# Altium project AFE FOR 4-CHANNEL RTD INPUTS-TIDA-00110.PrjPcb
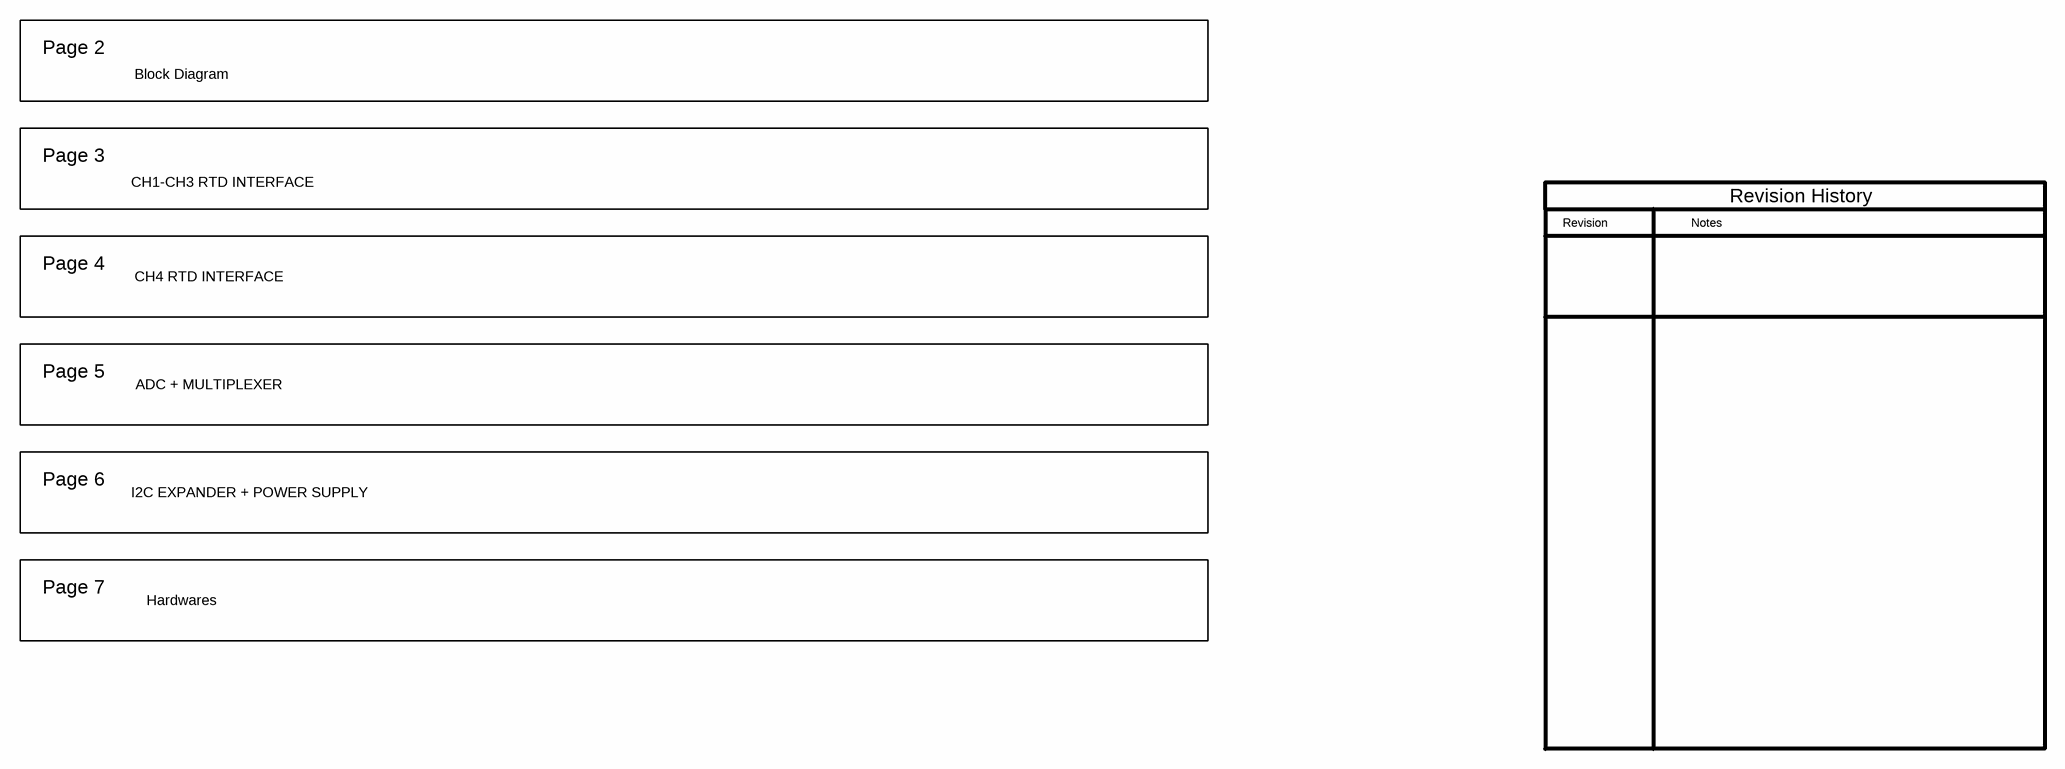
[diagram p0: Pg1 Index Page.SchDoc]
CopyrightYear: 2014; PCB_Rev: E1; PRJ_Customer: Public Release; PRJ_Engineer: Prahlad Supeda; PRJ_Number: TIDA-00110; PRJ_Title: AFE FOR 4-CHANNEL RTD INPUTS; SCH_Rev: E1; TechSupport: http://www.ti.com/support
7 sheets, 192 parts. Net scope: flat (ports and power ports of the same name join across sheets).
Board file: TIDA-00110.PcbDoc
Sheets:
  Pg1 Index Page.SchDoc
  Pg2 Block Diagram.SchDoc
  Pg3 CH1-CH3 RTD INTERFACE.SchDoc
  Pg4 CH4 RTD INTERFACE.SchDoc
  Pg5 ADC + MULTIPLEXER.SchDoc
  Pg6 I2C EXPANDER + POWER SUPPLY.SchDoc
  Pg7 Hardware.SchDoc

## Sheet Pg1 Index Page.SchDoc: Index Page
size 431 x 279 mm; Date: Not shown in title block; ApprovedBy: Not shown in title block; CheckedBy: Not shown in title block; Author: Not shown in title block; CompanyName: Not shown in title block; Engineer: Not shown in title block; Organization: Not shown in title block; Address1: Not shown in title block; Address2: Not shown in title block; Address3: Not shown in title block; Address4: Not shown in title block; DocumentNumber: 1; Revision: Use project parameter SCH_Rev; SheetNumber: 1; SheetTotal: 7; PageSetup: Record=PageOptions|CenterHorizontal=True|CenterVertical=True|PrintScale=0.62|XCorrection=1.00|YCorrection=1.00|PrintKind=0|BorderSize=5000000|LeftOffset=0|BottomOffset=0|Orientation=2|PaperLength=1000|PaperWidth=1000|Scale=100|PaperSource=15|PrintQuality=600|MediaType=1|DitherType=10|PaperKind=Letter|PrintScaleMode=1

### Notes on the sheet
- Page 2
- Block Diagram
- Page 3
- CH1-CH3 RTD INTERFACE
- Revision History
- Page 4
- Revision
- Notes
- CH4 RTD INTERFACE
- Page 5
- ADC + MULTIPLEXER
- Page 6
- I2C EXPANDER + POWER SUPPLY
- Page 7
- Hardwares

## Sheet Pg2 Block Diagram.SchDoc: Block Diagram
size 431 x 279 mm; Date: Not shown in title block; ApprovedBy: Not shown in title block; CheckedBy: Not shown in title block; Author: Not shown in title block; CompanyName: Not shown in title block; Engineer: Not shown in title block; Organization: Not shown in title block; Address1: Not shown in title block; Address2: Not shown in title block; Address3: Not shown in title block; Address4: Not shown in title block; DocumentNumber: 7; Revision: Use project parameter SCH_Rev; SheetNumber: 2; SheetTotal: 7; PageSetup: Record=PageOptions|CenterHorizontal=True|CenterVertical=True|PrintScale=1.00|XCorrection=1.00|YCorrection=1.00|PrintKind=0|BorderSize=5000000|LeftOffset=0|BottomOffset=0|Orientation=2|PaperLength=1000|PaperWidth=1000|Scale=100|PaperSource=15|PrintQuality=600|MediaType=1|DitherType=10|PaperKind=Letter|PrintScaleMode=1
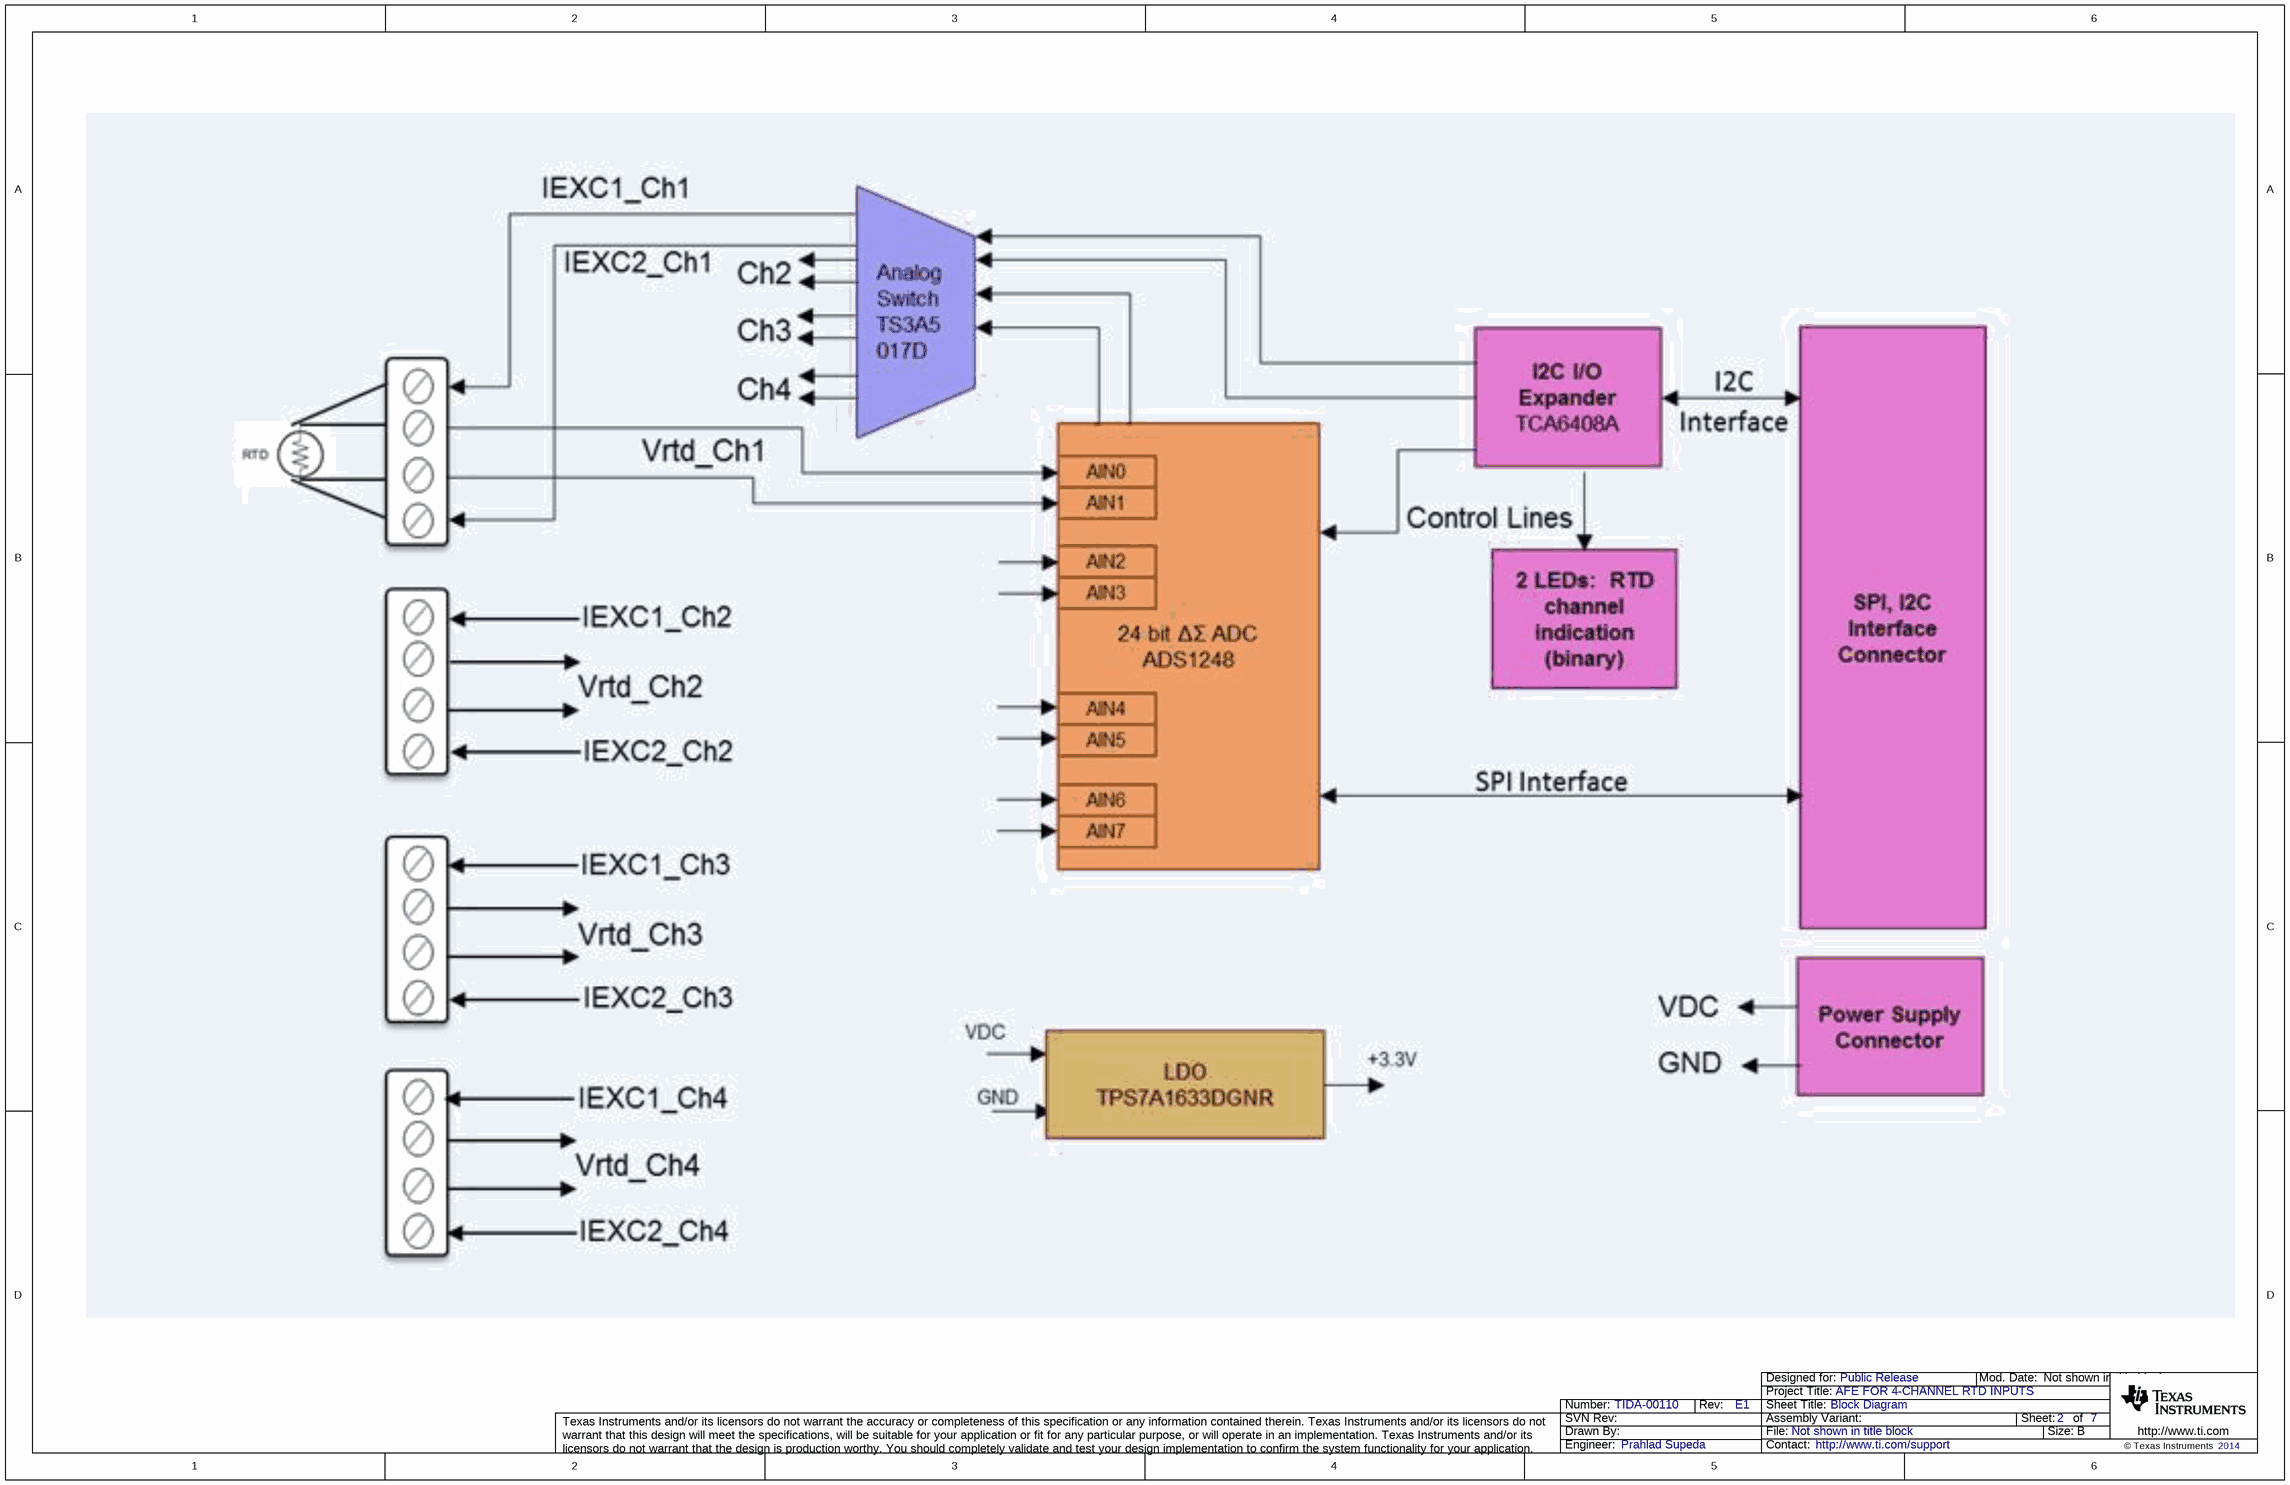
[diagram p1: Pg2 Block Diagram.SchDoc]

## Sheet Pg3 CH1-CH3 RTD INTERFACE.SchDoc: CH1-CH3 RTD INTERFACE
size 431 x 279 mm; Date: Not shown in title block; ApprovedBy: Not shown in title block; CheckedBy: Not shown in title block; Author: Not shown in title block; CompanyName: Not shown in title block; Engineer: Not shown in title block; Organization: Not shown in title block; Address1: Not shown in title block; Address2: Not shown in title block; Address3: Not shown in title block; Address4: Not shown in title block; DocumentNumber: 7; Revision: Use project parameter SCH_Rev; SheetNumber: 3; SheetTotal: 7; PageSetup: Record=PageOptions|CenterHorizontal=True|CenterVertical=True|PrintScale=0.64|XCorrection=1.00|YCorrection=1.00|PrintKind=0|BorderSize=5000000|LeftOffset=0|BottomOffset=0|Orientation=2|PaperLength=1000|PaperWidth=1000|Scale=100|PaperSource=15|PrintQuality=600|MediaType=1|DitherType=10|PaperKind=Letter|PrintScaleMode=1
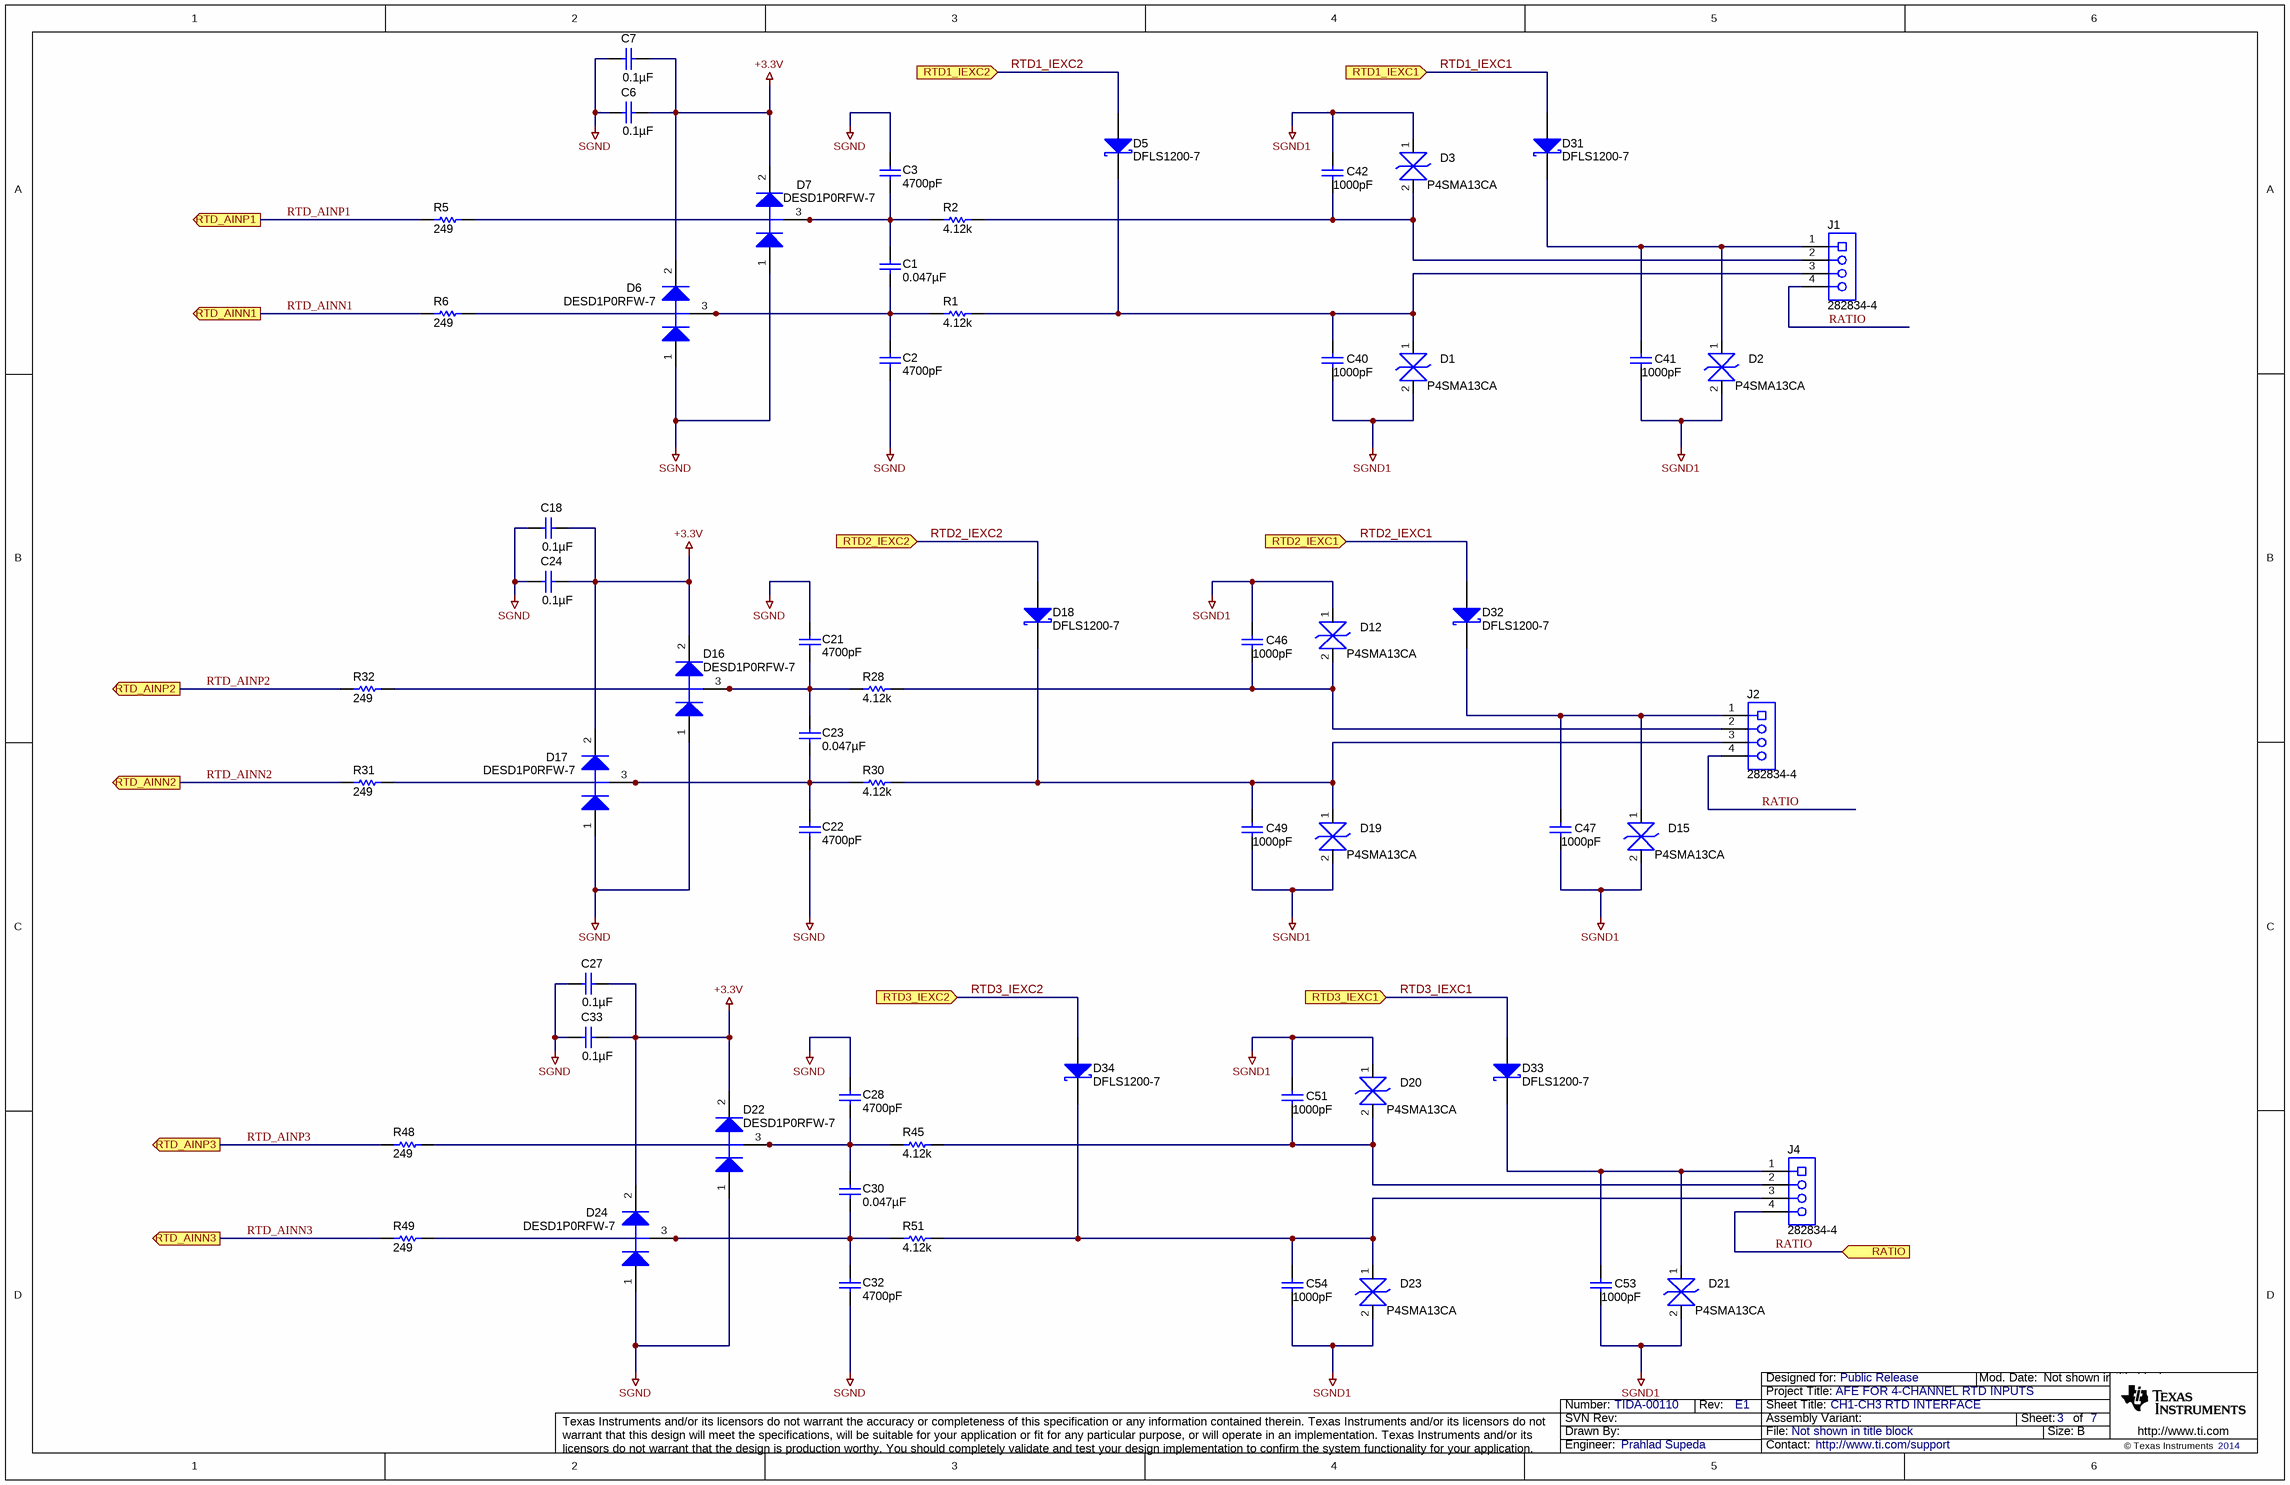
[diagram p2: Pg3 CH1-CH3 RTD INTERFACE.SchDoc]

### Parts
C1  ValueDisplayed: 0.047µF  [0603]  (hidden comment: C1608X7R1H473K)
C2  ValueDisplayed: 4700pF  [0603]  (hidden comment: C1608X8R1H472K)
C3  ValueDisplayed: 4700pF  [0603]  (hidden comment: C1608X8R1H472K)
C6  ValueDisplayed: 0.1µF  [0603]  (hidden comment: 06035C104KAT2A)
C7  ValueDisplayed: 0.1µF  [0603]  (hidden comment: 06035C104KAT2A)
C18  ValueDisplayed: 0.1µF  [0603]  (hidden comment: 06035C104KAT2A)
C21  ValueDisplayed: 4700pF  [0603]  (hidden comment: C1608X8R1H472K)
C22  ValueDisplayed: 4700pF  [0603]  (hidden comment: C1608X8R1H472K)
C23  ValueDisplayed: 0.047µF  [0603]  (hidden comment: C1608X7R1H473K)
C24  ValueDisplayed: 0.1µF  [0603]  (hidden comment: 06035C104KAT2A)
C27  ValueDisplayed: 0.1µF  [0603]  (hidden comment: 06035C104KAT2A)
C28  ValueDisplayed: 4700pF  [0603]  (hidden comment: C1608X8R1H472K)
C30  ValueDisplayed: 0.047µF  [0603]  (hidden comment: C1608X7R1H473K)
C32  ValueDisplayed: 4700pF  [0603]  (hidden comment: C1608X8R1H472K)
C33  ValueDisplayed: 0.1µF  [0603]  (hidden comment: 06035C104KAT2A)
C40  value 1000pF  [1206]  (hidden comment: CC1206KRX7R0BB102)
C41  value 1000pF  [1206]  (hidden comment: CC1206KRX7R0BB102)
C42  value 1000pF  [1206]  (hidden comment: CC1206KRX7R0BB102)
C46  value 1000pF  [1206]  (hidden comment: CC1206KRX7R0BB102)
C47  value 1000pF  [1206]  (hidden comment: CC1206KRX7R0BB102)
C49  value 1000pF  [1206]  (hidden comment: CC1206KRX7R0BB102)
C51  value 1000pF  [1206]  (hidden comment: CC1206KRX7R0BB102)
C53  value 1000pF  [1206]  (hidden comment: CC1206KRX7R0BB102)
C54  value 1000pF  [1206]  (hidden comment: CC1206KRX7R0BB102)
D1  P4SMA13CA  [DIO_DO214AC_SMA_BI]
D2  P4SMA13CA  [DIO_DO214AC_SMA_BI]
D3  P4SMA13CA  [DIO_DO214AC_SMA_BI]
D5  DFLS1200-7  [powerDI123]
D6  DESD1P0RFW-7  [SOT-323]
D7  DESD1P0RFW-7  [SOT-323]
D12  P4SMA13CA  [DIO_DO214AC_SMA_BI]
D15  P4SMA13CA  [DIO_DO214AC_SMA_BI]
D16  DESD1P0RFW-7  [SOT-323]
D17  DESD1P0RFW-7  [SOT-323]
D18  DFLS1200-7  [powerDI123]
D19  P4SMA13CA  [DIO_DO214AC_SMA_BI]
D20  P4SMA13CA  [DIO_DO214AC_SMA_BI]
D21  P4SMA13CA  [DIO_DO214AC_SMA_BI]
D22  DESD1P0RFW-7  [SOT-323]
D23  P4SMA13CA  [DIO_DO214AC_SMA_BI]
D24  DESD1P0RFW-7  [SOT-323]
D31  DFLS1200-7  [powerDI123]
D32  DFLS1200-7  [powerDI123]
D33  DFLS1200-7  [powerDI123]
D34  DFLS1200-7  [powerDI123]
J1  282834-4  [TEC_282834-4]
J2  282834-4  [TEC_282834-4]
J4  282834-4  [TEC_282834-4]
R1  value 4.12k  [0603]  (hidden comment: RG1608P-4121-B-T5)
R2  value 4.12k  [0603]  (hidden comment: RG1608P-4121-B-T5)
R5  ValueDisplayed: 249  [0603]  (hidden comment: CRCW0603249RFKEA)
R6  ValueDisplayed: 249  [0603]  (hidden comment: CRCW0603249RFKEA)
R28  value 4.12k  [0603]  (hidden comment: RG1608P-4121-B-T5)
R30  value 4.12k  [0603]  (hidden comment: RG1608P-4121-B-T5)
R31  ValueDisplayed: 249  [0603]  (hidden comment: CRCW0603249RFKEA)
R32  ValueDisplayed: 249  [0603]  (hidden comment: CRCW0603249RFKEA)
R45  value 4.12k  [0603]  (hidden comment: RG1608P-4121-B-T5)
R48  ValueDisplayed: 249  [0603]  (hidden comment: CRCW0603249RFKEA)
R49  ValueDisplayed: 249  [0603]  (hidden comment: CRCW0603249RFKEA)
R51  value 4.12k  [0603]  (hidden comment: RG1608P-4121-B-T5)

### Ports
RATIO (in), RTD1_IEXC1 (in), RTD1_IEXC2 (in), RTD2_IEXC1 (in), RTD2_IEXC2 (in), RTD3_IEXC1 (in), RTD3_IEXC2 (in), RTD_AINN1 (out), RTD_AINN2 (out), RTD_AINN3 (out), RTD_AINP1 (out), RTD_AINP2 (out), RTD_AINP3 (out)

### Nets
+3.3V: C6.1 C7.1 C18.1 C24.1 C27.1 C33.1 D6.2(K) D7.2(K) D16.2(K) D17.2(K) D22.2(K) D24.2(K)
SGND: C2.2 C3.1 C6.2 C7.2 C18.2 C21.1 C22.2 C24.2 C27.2 C28.1 C32.2 C33.2 D6.1(A) D7.1(A) D16.1(A) D17.1(A) D22.1(A) D24.1(A)
SGND1: C40.1 C41.1 C42.2 C46.2 C47.1 C49.1 C51.2 C53.1 C54.1 D1.2 D2.2 D3.1 D12.1 D15.2 D19.2 D20.1 D21.2 D23.2
RATIO: J1.4 J2.4 J4.4 ; port RATIO
RTD1_IEXC1: D31.2(A) ; port RTD1_IEXC1
RTD1_IEXC2: D5.2(A) ; port RTD1_IEXC2
RTD2_IEXC1: D32.2(A) ; port RTD2_IEXC1
RTD2_IEXC2: D18.2(A) ; port RTD2_IEXC2
RTD3_IEXC1: D33.2(A) ; port RTD3_IEXC1
RTD3_IEXC2: D34.2(A) ; port RTD3_IEXC2
RTD_AINN1: R6.1 ; port RTD_AINN1
RTD_AINN2: R31.1 ; port RTD_AINN2
RTD_AINN3: R49.1 ; port RTD_AINN3
RTD_AINP1: R5.1 ; port RTD_AINP1
RTD_AINP2: R32.1 ; port RTD_AINP2
RTD_AINP3: R48.1 ; port RTD_AINP3
NetC1_1: C1.1 C3.2 D7.3(C) R2.1 R5.2
NetC1_2: C1.2 C2.1 D6.3(C) R1.1 R6.2
NetC21_2: C21.2 C23.1 D16.3(C) R28.1 R32.2
NetC22_1: C22.1 C23.2 D17.3(C) R30.1 R31.2
NetC28_2: C28.2 C30.1 D22.3(C) R45.1 R48.2
NetC30_2: C30.2 C32.1 D24.3(C) R49.2 R51.1
NetC40_2: C40.2 D1.1 D5.1(K) J1.3 R1.2
NetC41_2: C41.2 D2.1 D31.1(K) J1.1
NetC42_1: C42.1 D3.2 J1.2 R2.2
NetC46_1: C46.1 D12.2 J2.2 R28.2
NetC47_2: C47.2 D15.1 D32.1(K) J2.1
NetC49_2: C49.2 D18.1(K) D19.1 J2.3 R30.2
NetC51_1: C51.1 D20.2 J4.2 R45.2
NetC53_2: C53.2 D21.1 D33.1(K) J4.1
NetC54_2: C54.2 D23.1 D34.1(K) J4.3 R51.2

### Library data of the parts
C1 C23 C30 = C1608X7R1H473K: CAP, CERM, 0.047uF, 50V, +/-10%, X7R, 0603; Manufacturer: TDK; Polarized: N; CompType: Capacitor; U/M: EA; Cap_F: 0.000000047; Tolerance_%: 10; ESR_Ohm: 0.0234; Value1: 0.0234 ohm; VDC_V: 50; TaMin_C: -55; TaMax_C: 125
C2 C3 C21 C22 C28 C32 = C1608X8R1H472K: CAP, CERM, 4700pF, 50V, +/-10%, X8R, 0603; Manufacturer: TDK; Polarized: N; CompType: Capacitor; U/M: EA; Cap_F: 0.0000000047; Tolerance_%: 10; ESR_Ohm: 0.0973; Value1: 0.0973 ohm; VDC_V: 50; TaMin_C: -55; TaMax_C: 150
C6 C7 C18 C24 C27 C33 = C0603C104K5RACTU: CAP, CERM, 0.1uF, 50V, +/-10%, X7R, 0603; Manufacturer: AVX; Polarized: N; CompType: Capacitor; U/M: EA; Cap_F: 0.0000001; Tolerance_%: 10; Value1: Unknown; VDC_V: 50; TaMin_C: -55; TaMax_C: 125
C40-C42 C46 C47 C49 C51 C53 C54 = 202R18W102KV4E: CAP CER 1000PF 100V 10% X7R 1206; Manufacturer: Yageo; Polarized: N; CompType: Capacitor; Cap_F: 0.000000001; Tolerance_%: 0; Value2: 2KV
D1-D3 D12 D15 D19-D21 D23 = SMBJ18CA: TVS DIODE 11.1VWM 18.2VC SMD; Manufacturer: Littelfuse Inc
D5 D18 D31-D34 = DFLS1200-7: Diode, Schotky, 200V, 1A, PowerDI123; Manufacturer: DIODES  INCORPORATED; U/M: EA; Vf_V: 0.85; Value2: 0.85V; Io_A: 1; Vr_V: 200; TJmax_C: 175; RJC_CperW: 7; Type: Schottky
D6 D7 D16 D17 D22 D24 = BAV99WT1G: TVS DIODE,70VVVM,8VC,SOT-323; Manufacturer: DIODES INCORPORATED; Type: P-N; Value: DNP
J1 J2 J4 = 282834-4: Receptacle, 100mil, 4X1 TH; Manufacturer: TE Connectivity; SymbolCreator: a0411947; U/M: EA
R1 R2 R28 R30 R45 R51 = RG1608P-4121-B-T5: RES, 4.12k ohm, 0.1%, 0.1W, 0603; Manufacturer: Susumu Co Ltd; CompType: Resistor; Res_ohm: 4120; Value_Code: 4k12; Tolerance_%: 0.1; VDC_V: 75; TempCo: 25 ppm/C; EIA_Code: E192; U/M: EA
R5 R6 R31 R32 R48 R49 = CRCW0603249RFKEA: RES, 249, 1%, 0.1 W, 0603; Manufacturer: Vishay-Dale; CompType: Resistor; Value: 249; Value_Code: 249R; Tolerance_%: 1; Power_W: 0.1; Value2: 0.1W; VDC_V: 75; TempCo: 100 ppm/C; EIA_Code: E96; U/M: EA

## Sheet Pg4 CH4 RTD INTERFACE.SchDoc: CH4 RTD INTERFACE
size 431 x 279 mm; Date: Not shown in title block; ApprovedBy: Not shown in title block; CheckedBy: Not shown in title block; Author: Not shown in title block; CompanyName: Not shown in title block; Engineer: Not shown in title block; Organization: Not shown in title block; Address1: Not shown in title block; Address2: Not shown in title block; Address3: Not shown in title block; Address4: Not shown in title block; DocumentNumber: 7; Revision: Use project parameter SCH_Rev; SheetNumber: 4; SheetTotal: 7; PageSetup: Record=PageOptions|CenterHorizontal=True|CenterVertical=True|PrintScale=1.00|XCorrection=1.00|YCorrection=1.00|PrintKind=0|BorderSize=5000000|LeftOffset=0|BottomOffset=0|Orientation=2|PaperLength=1000|PaperWidth=1000|Scale=100|PaperSource=15|PrintQuality=600|MediaType=1|DitherType=10|PaperKind=Letter|PrintScaleMode=1
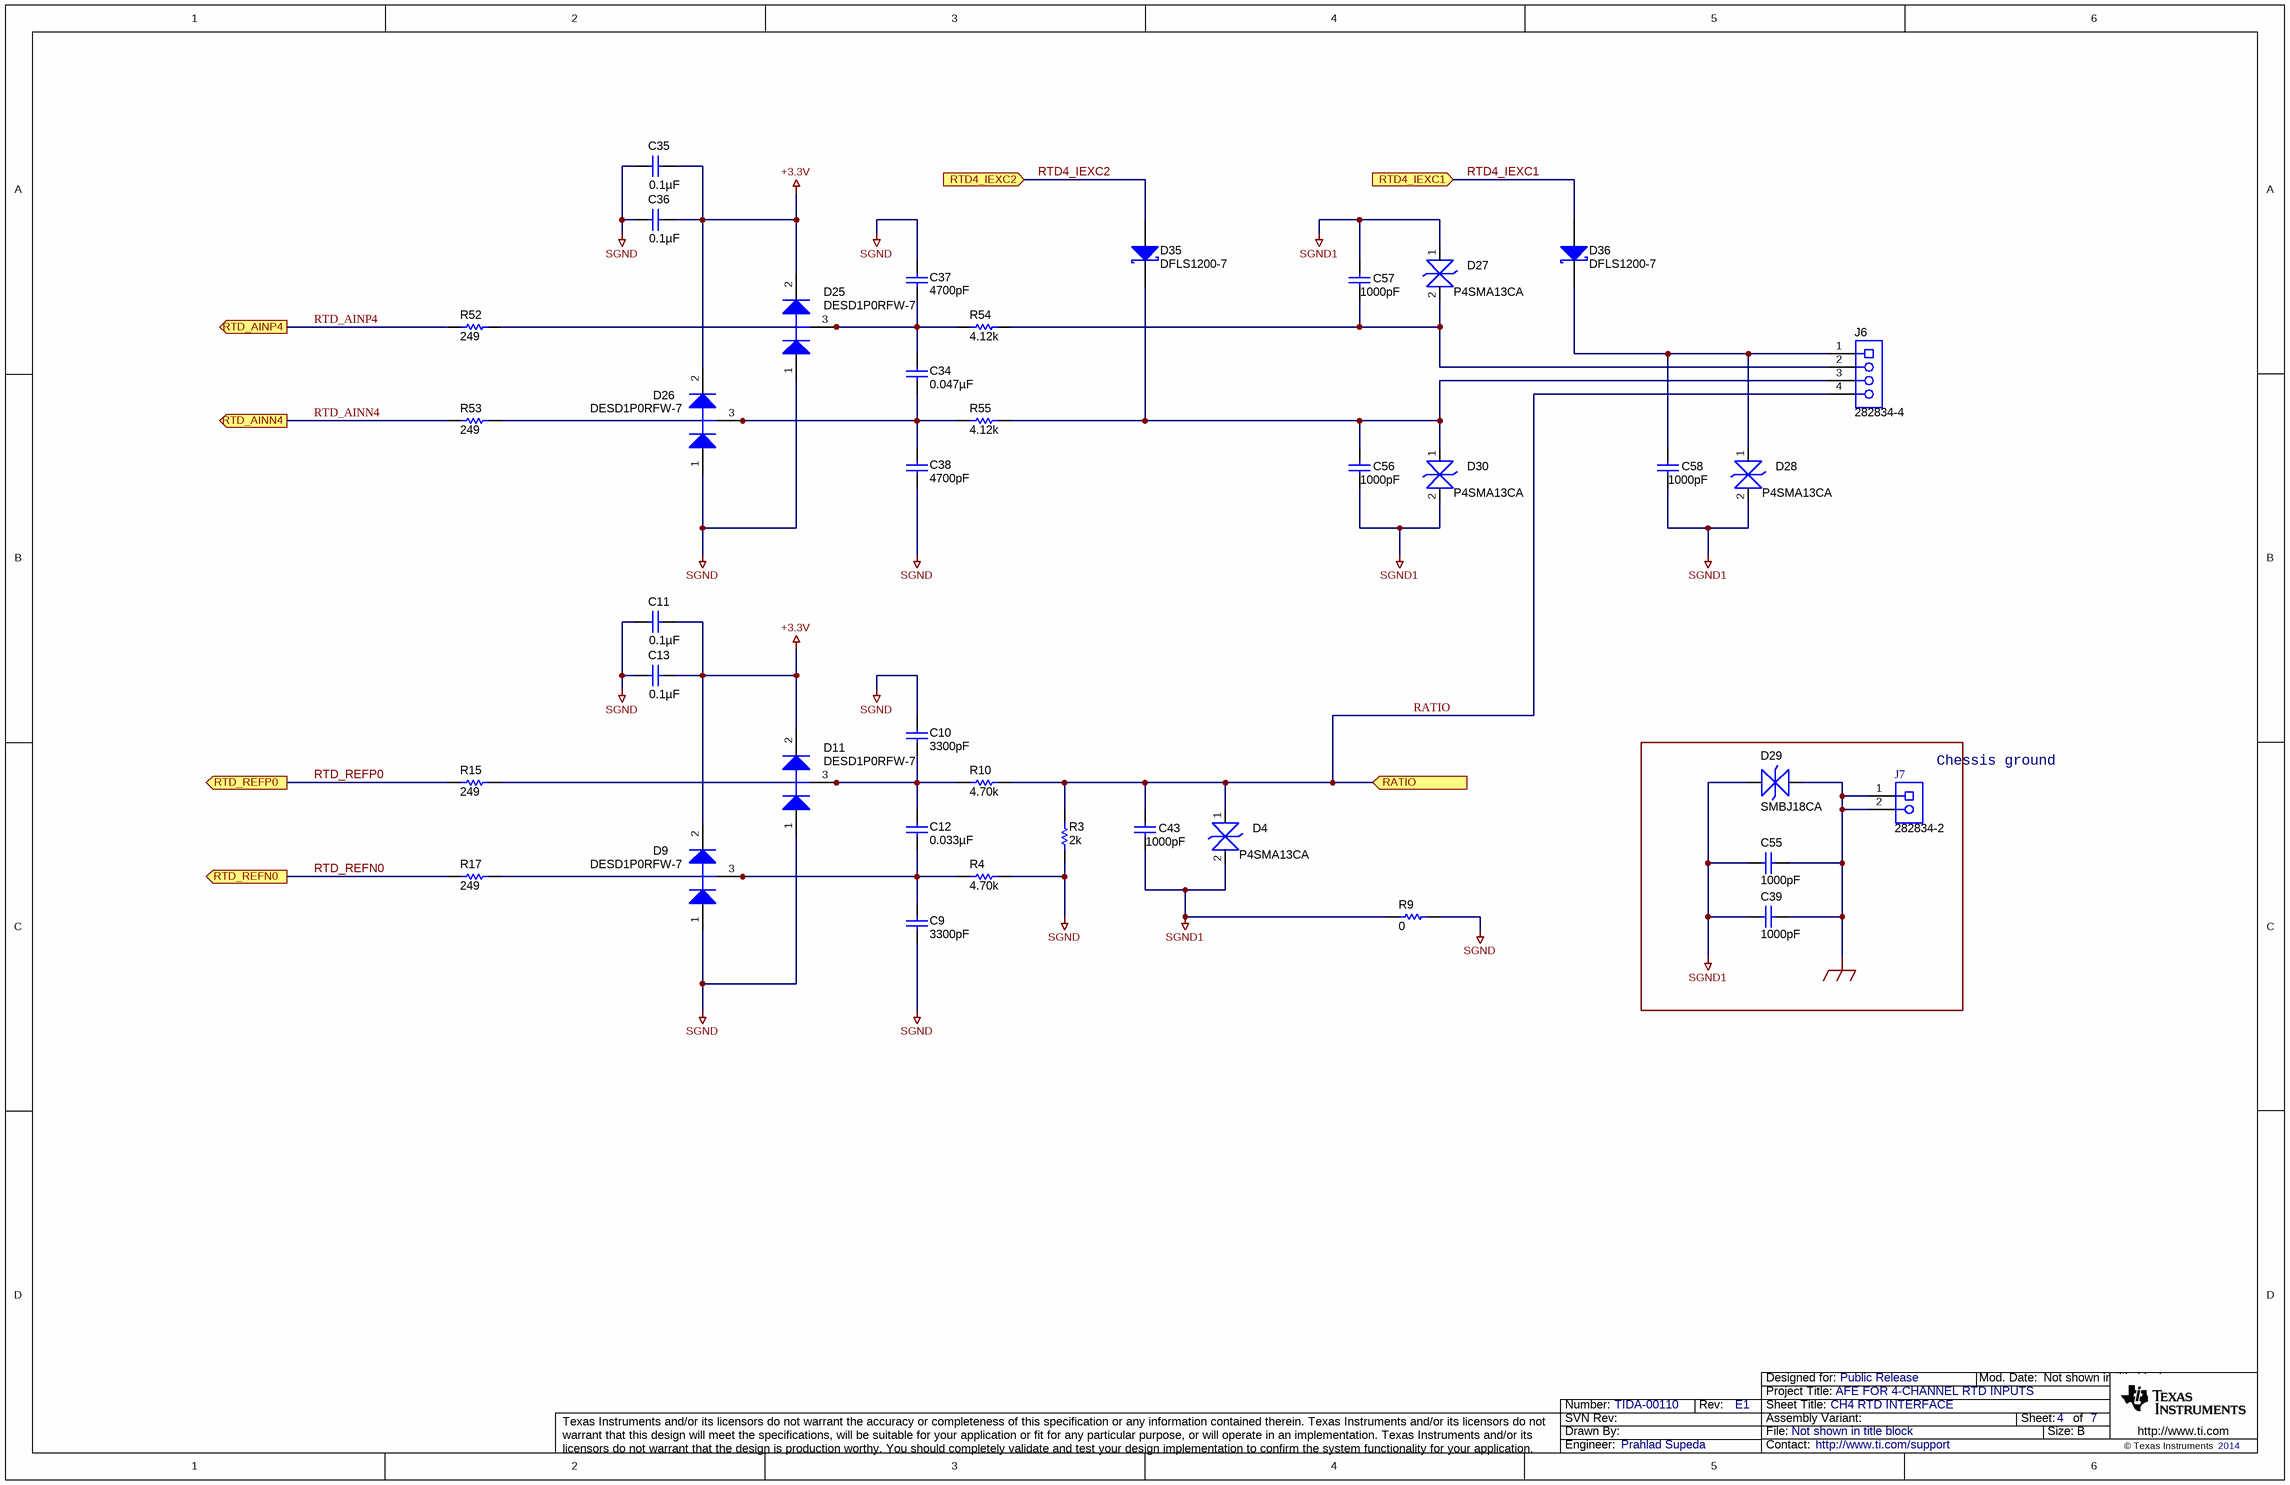
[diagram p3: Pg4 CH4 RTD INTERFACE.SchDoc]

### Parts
C9  ValueDisplayed: 3300pF  [0603]  (hidden comment: C0603C332K5RACTU)
C10  ValueDisplayed: 3300pF  [0603]  (hidden comment: C0603C332K5RACTU)
C11  ValueDisplayed: 0.1µF  [0603]  (hidden comment: 06035C104KAT2A)
C12  ValueDisplayed: 0.033µF  [0603]  (hidden comment: GRM188R71H333KA61D)
C13  ValueDisplayed: 0.1µF  [0603]  (hidden comment: 06035C104KAT2A)
C34  ValueDisplayed: 0.047µF  [0603]  (hidden comment: C1608X7R1H473K)
C35  ValueDisplayed: 0.1µF  [0603]  (hidden comment: 06035C104KAT2A)
C36  ValueDisplayed: 0.1µF  [0603]  (hidden comment: 06035C104KAT2A)
C37  ValueDisplayed: 4700pF  [0603]  (hidden comment: C1608X8R1H472K)
C38  ValueDisplayed: 4700pF  [0603]  (hidden comment: C1608X8R1H472K)
C39  value 1000pF  [1206]  (hidden comment: 202R18W102KV4E)
C43  value 1000pF  [1206]  (hidden comment: CC1206KRX7R0BB102)
C55  value 1000pF  [1206]  (hidden comment: 202R18W102KV4E)
C56  value 1000pF  [1206]  (hidden comment: CC1206KRX7R0BB102)
C57  value 1000pF  [1206]  (hidden comment: CC1206KRX7R0BB102)
C58  value 1000pF  [1206]  (hidden comment: CC1206KRX7R0BB102)
D4  P4SMA13CA  [DIO_DO214AC_SMA_BI]
D9  DESD1P0RFW-7  [SOT-323]
D11  DESD1P0RFW-7  [SOT-323]
D25  DESD1P0RFW-7  [SOT-323]
D26  DESD1P0RFW-7  [SOT-323]
D27  P4SMA13CA  [DIO_DO214AC_SMA_BI]
D28  P4SMA13CA  [DIO_DO214AC_SMA_BI]
D29  SMBJ18CA  [DIO_SMB_BIAAAA]
D30  P4SMA13CA  [DIO_DO214AC_SMA_BI]
D35  DFLS1200-7  [powerDI123]
D36  DFLS1200-7  [powerDI123]
J6  282834-4  [TEC_282834-4]
J7  282834-2  [TEC_282834-2]
R3  value 2k  [1206]  (hidden comment: TNPW12062K00BEEA)
R4  value 4.70k  [0603]  (hidden comment: RG1608P-472-B-T5)
R9  value 0  [0805_HV]  (hidden comment: RC0805JR-070RL)
R10  value 4.70k  [0603]  (hidden comment: RG1608P-472-B-T5)
R15  ValueDisplayed: 249  [0603]  (hidden comment: CRCW0603249RFKEA)
R17  ValueDisplayed: 249  [0603]  (hidden comment: CRCW0603249RFKEA)
R52  ValueDisplayed: 249  [0603]  (hidden comment: CRCW0603249RFKEA)
R53  ValueDisplayed: 249  [0603]  (hidden comment: CRCW0603249RFKEA)
R54  value 4.12k  [0603]  (hidden comment: RG1608P-4121-B-T5)
R55  value 4.12k  [0603]  (hidden comment: RG1608P-4121-B-T5)

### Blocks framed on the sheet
Chessis ground: C39 C55 D29 J7

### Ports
RATIO (in), RTD4_IEXC1 (in), RTD4_IEXC2 (in), RTD_AINN4 (out), RTD_AINP4 (out), RTD_REFN0 (out), RTD_REFP0 (out)

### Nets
+3.3V: C11.1 C13.1 C35.1 C36.1 D9.2(K) D11.2(K) D25.2(K) D26.2(K)
GND_EARTH: C39.2 C55.2 D29.2 J7.1 J7.2
SGND: C9.2 C10.1 C11.2 C13.2 C35.2 C36.2 C37.1 C38.2 D9.1(A) D11.1(A) D25.1(A) D26.1(A) R3.1 R4.2 R9.2
SGND1: C39.1 C43.1 C55.1 C56.1 C57.2 C58.1 D4.2 D27.1 D28.2 D29.1 D30.2 R9.1
RATIO: C43.2 D4.1 J6.4 R3.2 R10.2 ; port RATIO
RTD4_IEXC1: D36.2(A) ; port RTD4_IEXC1
RTD4_IEXC2: D35.2(A) ; port RTD4_IEXC2
RTD_AINN4: R53.1 ; port RTD_AINN4
RTD_AINP4: R52.1 ; port RTD_AINP4
RTD_REFN0: R17.1 ; port RTD_REFN0
RTD_REFP0: R15.1 ; port RTD_REFP0
NetC9_1: C9.1 C12.2 D9.3(C) R4.1 R17.2
NetC10_2: C10.2 C12.1 D11.3(C) R10.1 R15.2
NetC34_1: C34.1 C37.2 D25.3(C) R52.2 R54.1
NetC34_2: C34.2 C38.1 D26.3(C) R53.2 R55.1
NetC56_2: C56.2 D30.1 D35.1(K) J6.3 R55.2
NetC57_1: C57.1 D27.2 J6.2 R54.2
NetC58_2: C58.2 D28.1 D36.1(K) J6.1

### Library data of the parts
C9 C10 = C0603C332K5RACTU: CAP, CERM, 3300pF, 50V, +/-10%, X7R, 0603; Manufacturer: Kemet; Polarized: N; CompType: Capacitor; U/M: EA; Cap_F: 0.0000000033; Tolerance_%: 10; Value1: Unknown; VDC_V: 50; TaMin_C: -55; TaMax_C: 125
C11 C13 C35 C36 = C0603C104K5RACTU: as C6 on sheet Pg3 CH1-CH3 RTD INTERFACE
C12 = GRM188R71H333KA61D: CAP, CERM, 0.033uF, 50V, +/-10%, X7R, 0603; Manufacturer: MuRata; Polarized: N; CompType: Capacitor; U/M: EA; Cap_F: 0.000000033; Tolerance_%: 10; Value1: Unknown; VDC_V: 50; TaMin_C: -55; TaMax_C: 125
C34 = C1608X7R1H473K: as C1 on sheet Pg3 CH1-CH3 RTD INTERFACE
C37 C38 = C1608X8R1H472K: as C2 on sheet Pg3 CH1-CH3 RTD INTERFACE
C39 C55 = 202R18W102KV4E: CAP, CERM, 1000pF, 2KV 10% X7R 1206; Manufacturer: Johanson Dielectrics Inc; Polarized: N; CompType: Capacitor; Cap_F: 0.000000001; Tolerance_%: 0
C43 C56-C58 = 202R18W102KV4E: as C40 on sheet Pg3 CH1-CH3 RTD INTERFACE
D4 D27 D28 D30 = SMBJ18CA: as D1 on sheet Pg3 CH1-CH3 RTD INTERFACE
D9 D11 D25 D26 = BAV99WT1G: as D6 on sheet Pg3 CH1-CH3 RTD INTERFACE
D29 = SMBJ18CA: TVS 18 VOLT 600 WATT BI-DIR SMB; Manufacturer: Littelfuse Inc
D35 D36 = DFLS1200-7: as D5 on sheet Pg3 CH1-CH3 RTD INTERFACE
J6 = 282834-4: as J1 on sheet Pg3 CH1-CH3 RTD INTERFACE
J7 = 282834-2: Terminal Block, 2x1, 2.54mm, TH; Manufacturer: TE Connectivity; SymbolCreator: a0412235; U/M: EA
R3 = CRCW12062K49FKEA: RES 2K OHM 1/4W 0.1% 1206; Manufacturer: Vishay-Dale; CompType: Resistor; Res_ohm: 2490; Value_Code: 2k49; Tolerance_%: 1; Power_W: 0.25; Value2: 0.25W; VDC_V: 200; TempCo: 100 ppm/C; EIA_Code: E96; U/M: EA
R4 R10 = RG1608P-472-B-T5: RES, 4.70k ohm, 0.1%, 0.1W, 0603; Manufacturer: Susumu Co Ltd; CompType: Resistor; Res_ohm: 4700; Value_Code: 4k70; Tolerance_%: 0.1; VDC_V: 75; TempCo: 25 ppm/C; EIA_Code: E192; U/M: EA
R9 = RC0805JR-070RL: RES, 0 ohm, 5%, 0.125W, 0805; Manufacturer: Yageo America; CompType: Resistor; Value_Code: 0000; Tolerance_%: 5; Power_W: 0.125; VDC_V: 150; TempCo: 200 ppm/C; EIA_Code: E24; U/M: EA
R15 R17 R52 R53 = CRCW0603249RFKEA: as R5 on sheet Pg3 CH1-CH3 RTD INTERFACE
R54 R55 = RG1608P-4121-B-T5: as R1 on sheet Pg3 CH1-CH3 RTD INTERFACE

## Sheet Pg5 ADC + MULTIPLEXER.SchDoc: ADC + MULTIPLEXER
size 431 x 279 mm; Date: Not shown in title block; ApprovedBy: Not shown in title block; CheckedBy: Not shown in title block; Author: Not shown in title block; CompanyName: Not shown in title block; Engineer: Not shown in title block; Organization: Not shown in title block; Address1: Not shown in title block; Address2: Not shown in title block; Address3: Not shown in title block; Address4: Not shown in title block; DocumentNumber: 7; Revision: Use project parameter SCH_Rev; SheetNumber: 5; SheetTotal: 7; PageSetup: Record=PageOptions|CenterHorizontal=True|CenterVertical=True|PrintScale=1.00|XCorrection=1.00|YCorrection=1.00|PrintKind=0|BorderSize=5000000|LeftOffset=0|BottomOffset=0|Orientation=2|PaperLength=1000|PaperWidth=1000|Scale=100|PaperSource=15|PrintQuality=600|MediaType=1|DitherType=10|PaperKind=Letter|PrintScaleMode=1
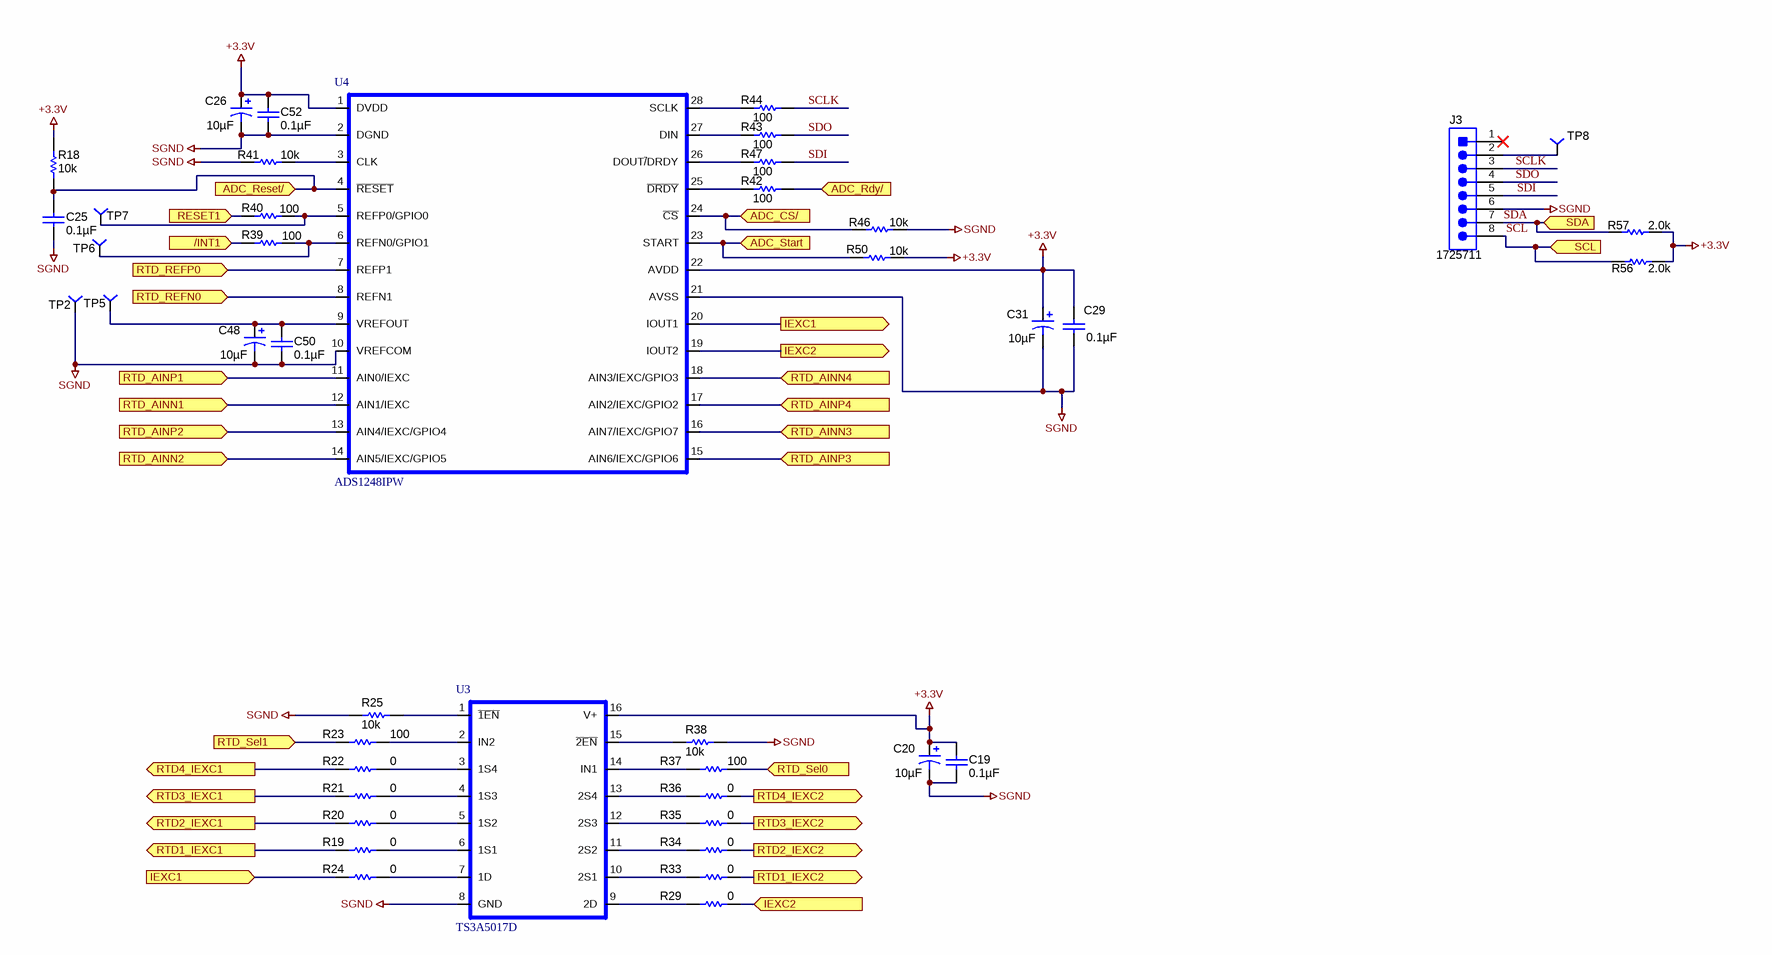
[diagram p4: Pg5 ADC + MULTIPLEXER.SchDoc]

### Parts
C19  ValueDisplayed: 0.1µF  [0603]  (hidden comment: 06035C104KAT2A)
C20  ValueDisplayed: 10µF  [3528-21]  (hidden comment: F931C106KBA)
C25  ValueDisplayed: 0.1µF  [0603]  (hidden comment: 06035C104KAT2A)
C26  ValueDisplayed: 10µF  [3528-21]  (hidden comment: F931C106KBA)
C29  ValueDisplayed: 0.1µF  [0603]  (hidden comment: 06035C104KAT2A)
C31  ValueDisplayed: 10µF  [3528-21]  (hidden comment: F931C106KBA)
C48  ValueDisplayed: 10µF  [3528-21]  (hidden comment: F931C106KBA)
C50  ValueDisplayed: 0.1µF  [0603]  (hidden comment: 06035C104KAT2A)
C52  ValueDisplayed: 0.1µF  [0603]  (hidden comment: 06035C104KAT2A)
J3  1725711  [CONN_1725711]
R18  ValueDisplayed: 10k  [0603]  (hidden comment: CRCW060310K0JNEA)
R19  ValueDisplayed: 0  [0603]  (hidden comment: CRCW06030000Z0EA)
R20  ValueDisplayed: 0  [0603]  (hidden comment: CRCW06030000Z0EA)
R21  ValueDisplayed: 0  [0603]  (hidden comment: CRCW06030000Z0EA)
R22  ValueDisplayed: 0  [0603]  (hidden comment: CRCW06030000Z0EA)
R23  ValueDisplayed: 100  [0603]  (hidden comment: CRCW0603100RFKEA)
R24  ValueDisplayed: 0  [0603]  (hidden comment: CRCW06030000Z0EA)
R25  ValueDisplayed: 10k  [0603]  (hidden comment: CRCW060310K0JNEA)
R29  ValueDisplayed: 0  [0603]  (hidden comment: CRCW06030000Z0EA)
R33  ValueDisplayed: 0  [0603]  (hidden comment: CRCW06030000Z0EA)
R34  ValueDisplayed: 0  [0603]  (hidden comment: CRCW06030000Z0EA)
R35  ValueDisplayed: 0  [0603]  (hidden comment: CRCW06030000Z0EA)
R36  ValueDisplayed: 0  [0603]  (hidden comment: CRCW06030000Z0EA)
R37  ValueDisplayed: 100  [0603]  (hidden comment: CRCW0603100RFKEA)
R38  ValueDisplayed: 10k  [0603]  (hidden comment: CRCW060310K0JNEA)
R39  ValueDisplayed: 100  [0603]  (hidden comment: CRCW0603100RFKEA)
R40  ValueDisplayed: 100  [0603]  (hidden comment: CRCW0603100RFKEA)
R41  ValueDisplayed: 10k  [0603]  (hidden comment: CRCW060310K0JNEA)
R42  ValueDisplayed: 100  [0603]  (hidden comment: CRCW0603100RFKEA)
R43  ValueDisplayed: 100  [0603]  (hidden comment: CRCW0603100RFKEA)
R44  ValueDisplayed: 100  [0603]  (hidden comment: CRCW0603100RFKEA)
R46  ValueDisplayed: 10k  [0603]  (hidden comment: CRCW060310K0JNEA)
R47  ValueDisplayed: 100  [0603]  (hidden comment: CRCW0603100RFKEA)
R50  ValueDisplayed: 10k  [0603]  (hidden comment: CRCW060310K0JNEA)
R56  ValueDisplayed: 2.0k  [0603]  (hidden comment: RC0603JR-072KL)
R57  ValueDisplayed: 2.0k  [0603]  (hidden comment: RC0603JR-072KL)
TP2  TP-038  [TP1_PD40_D0.5_S50]  (value not drawn)
TP5  TP-038  [TP1_PD40_D0.5_S50]  (value not drawn)
TP6  TP-038  [TP1_PD40_D0.5_S50]  (value not drawn)
TP7  TP-038  [TP1_PD40_D0.5_S50]  (value not drawn)
TP8  TP-038  [TP1_PD40_D0.5_S50]  (value not drawn)
U3  TS3A5017D  [SO16]
U4  ADS1248IPW  [PW28]

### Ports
/INT1 (in), ADC_CS/ (in), ADC_Rdy/ (in), ADC_Reset/ (in), ADC_Start (in), IEXC1 (in), IEXC1 (out), IEXC2 (in), IEXC2 (out), RESET1 (in), RTD1_IEXC1 (out), RTD1_IEXC2 (out), RTD2_IEXC1 (out), RTD2_IEXC2 (out), RTD3_IEXC1 (out), RTD3_IEXC2 (out), RTD4_IEXC1 (out), RTD4_IEXC2 (out), RTD_AINN1 (in), RTD_AINN2 (in), RTD_AINN3 (in), RTD_AINN4 (in), RTD_AINP1 (in), RTD_AINP2 (in), RTD_AINP3 (in), RTD_AINP4 (in), RTD_REFN0 (in), RTD_REFP0 (in), RTD_Sel0 (in), RTD_Sel1 (in), SCL (in), SDA (in)

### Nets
+3.3V: C19.1 C20.1(+) C26.1(+) C29.1 C31.1(+) C52.1 R18.1 R50.1 R56.2 R57.2 U3.16(V+) U4.1(DVDD) U4.22(AVDD)
SGND: C19.2 C20.2(-) C25.2 C26.2(-) C29.2 C31.2(-) C48.2(-) C50.2 C52.2 J3.6 R25.2 R38.1 R41.2 R46.1 TP2.1 U3.8(GND) U4.2(DGND) U4.10(VREFCOM) U4.21(AVSS)
/INT1: R39.1 ; port /INT1
ADC_CS/: R46.2 U4.24(~{CS}) ; port ADC_CS/
ADC_Rdy/: R42.2 ; port ADC_Rdy/
ADC_Reset/: C25.1 R18.2 U4.4(~{RESET}) ; port ADC_Reset/
ADC_Start: R50.2 U4.23(START) ; port ADC_Start
IEXC1: R24.1 U4.20(IOUT1) ; port IEXC1
IEXC2: R29.2 U4.19(IOUT2) ; port IEXC2
RESET1: R40.1 ; port RESET1
RTD1_IEXC1: R19.1 ; port RTD1_IEXC1
RTD1_IEXC2: R33.2 ; port RTD1_IEXC2
RTD2_IEXC1: R20.1 ; port RTD2_IEXC1
RTD2_IEXC2: R34.2 ; port RTD2_IEXC2
RTD3_IEXC1: R21.1 ; port RTD3_IEXC1
RTD3_IEXC2: R35.2 ; port RTD3_IEXC2
RTD4_IEXC1: R22.1 ; port RTD4_IEXC1
RTD4_IEXC2: R36.2 ; port RTD4_IEXC2
RTD_AINN1: U4.12(AIN1/IEXC) ; port RTD_AINN1
RTD_AINN2: U4.14(AIN5/IEXC/GPIO5) ; port RTD_AINN2
RTD_AINN3: U4.16(AIN7/IEXC/GPIO7) ; port RTD_AINN3
RTD_AINN4: U4.18(AIN3/IEXC/GPIO3) ; port RTD_AINN4
RTD_AINP1: U4.11(AIN0/IEXC) ; port RTD_AINP1
RTD_AINP2: U4.13(AIN4/IEXC/GPIO4) ; port RTD_AINP2
RTD_AINP3: U4.15(AIN6/IEXC/GPIO6) ; port RTD_AINP3
RTD_AINP4: U4.17(AIN2/IEXC/GPIO2) ; port RTD_AINP4
RTD_REFN0: U4.8(REFN1) ; port RTD_REFN0
RTD_REFP0: U4.7(REFP1) ; port RTD_REFP0
RTD_Sel0: R37.2 ; port RTD_Sel0
RTD_Sel1: R23.1 ; port RTD_Sel1
SCL: J3.8 R56.1 ; port SCL
SCLK: J3.3 R44.2
SDA: J3.7 R57.1 ; port SDA
SDI: J3.5 R47.2
SDO: J3.4 R43.2
NetC48_1: C48.1(+) C50.1 TP5.1 U4.9(VREFOUT)
NetJ3_2: J3.2 TP8.1
NetR19_2: R19.2 U3.6(1S1)
NetR20_2: R20.2 U3.5(1S2)
NetR21_2: R21.2 U3.4(1S3)
NetR22_2: R22.2 U3.3(1S4)
NetR23_2: R23.2 U3.2(IN2)
NetR24_2: R24.2 U3.7(1D)
NetR25_1: R25.1 U3.1(~{1EN})
NetR29_1: R29.1 U3.9(2D)
NetR33_1: R33.1 U3.10(2S1)
NetR34_1: R34.1 U3.11(2S2)
NetR35_1: R35.1 U3.12(2S3)
NetR36_1: R36.1 U3.13(2S4)
NetR37_1: R37.1 U3.14(IN1)
NetR38_2: R38.2 U3.15(~{2EN})
NetR39_2: R39.2 TP6.1 U4.6(REFN0/GPIO1)
NetR40_2: R40.2 TP7.1 U4.5(REFP0/GPIO0)
NetR41_1: R41.1 U4.3(CLK)
NetR42_1: R42.1 U4.25(~{DRDY})
NetR43_1: R43.1 U4.27(DIN)
NetR44_1: R44.1 U4.28(SCLK)
NetR47_1: R47.1 U4.26(DOUT~{/}DRDY)

Not connected (* = marked no-connect by the designer): J3 1*

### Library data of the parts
C19 C29 C50 C52 = 06035C104KAT2A: CAP, CERM, 0.1uF, 50V, +/-10%, X7R, 0603; Manufacturer: AVX; Polarized: N; CompType: Capacitor; U/M: EA; Cap_F: 0.0000001; Tolerance_%: 10; Value1: Unknown; VDC_V: 50; TaMin_C: -55; TaMax_C: 125
C20 C26 C31 C48 = 293D106X9016B2TE3: CAP, TA, 10 µF, 16 V, +/- 10%, 2 ohm, SMD; Manufacturer: AVX; Polarized: Y; CompType: Capacitor; Value: 10uF; U/M: EA; Cap_F: 0.00001; Tolerance_%: 10; Value1: 2 ohm; VDC_V: 16; Value2: 16V; ESR_ohm: 2; IRMS_A: 0.21; TaMin_C: -55; TaMax_C: 125; Cap_Case: B
C25 = C0603C104K5RACTU: as C6 on sheet Pg3 CH1-CH3 RTD INTERFACE
J3 = 1725711: Terminal Block, 8x1, 2.54 mm, TH; Manufacturer: Phoenix Contact; SymbolCreator: a0411947; U/M: EA
R18 R25 R38 R41 R46 R50 = CRCW060310K0JNEA: RES, 10 k, 5%, 0.1 W, 0603; Manufacturer: Vishay-Dale; CompType: Resistor; Res_ohm: 10000; Value: 10k; Value_Code: 10k0; Tolerance_%: 5; Power_W: 0.1; Value2: 0.1W; VDC_V: 75; TempCo: 200 ppm/C; EIA_Code: E24; U/M: EA
R19-R22 R24 R29 R33-R36 = CRCW06030000Z0EA: RES, 0, 5%, 0.1 W, 0603; Manufacturer: Vishay-Dale; CompType: Resistor; Value: 0; Value_Code: 0000; Tolerance_%: 5; Power_W: 0.1; Value2: 0.1W; VDC_V: 75; TempCo: 200 ppm/C; EIA_Code: E24; U/M: EA
R23 R37 R39 R40 R42-R44 R47 = CRCW0603100RFKEA: RES, 100, 1%, 0.1 W, 0603; Manufacturer: Vishay-Dale; CompType: Resistor; Value: 100; Value_Code: 100R; Tolerance_%: 1; Power_W: 0.1; Value2: 0.1W; VDC_V: 75; TempCo: 100 ppm/C; EIA_Code: E96; U/M: EA
R56 R57 = RC0603JR-072KL: RES, 2.0 k, 5%, 0.1 W, 0603; Manufacturer: Yageo America; CompType: Resistor; Res_ohm: 2000; Value: 2.0k; Value_Code: 2k00; Tolerance_%: 5; Power_W: 0.1; Value2: 0.1W; VDC_V: 50; TempCo: 100 ppm/C; EIA_Code: E24; U/M: EA
TP2 TP5-TP8 = TP-038: Test Point 40mil pad 20mil drill; Manufacturer: STD; Value: STD
U3 = TS3A5017D: IC, Dual, 14 Ohms SP4T Analog Switch; Manufacturer: TI; Alternate Manufacturer: None; AREA: 145200
U4 = ADS1248IPW: IC, 24-Bit A-D Converters for Temperature Sensors; Manufacturer: TI; Alternate Manufacturer: None; Area: 164.280

## Sheet Pg6 I2C EXPANDER + POWER SUPPLY.SchDoc: I2C EXPANDER + POWER SUPPLY
size 431 x 279 mm; Date: Not shown in title block; ApprovedBy: Not shown in title block; CheckedBy: Not shown in title block; Author: Not shown in title block; CompanyName: Not shown in title block; Engineer: Not shown in title block; Organization: Not shown in title block; Address1: Not shown in title block; Address2: Not shown in title block; Address3: Not shown in title block; Address4: Not shown in title block; DocumentNumber: 7; Revision: Use project parameter SCH_Rev; SheetNumber: 6; SheetTotal: 7; PageSetup: Record=PageOptions|CenterHorizontal=True|CenterVertical=True|PrintScale=1.00|XCorrection=1.00|YCorrection=1.00|PrintKind=0|BorderSize=5000000|LeftOffset=0|BottomOffset=0|Orientation=2|PaperLength=1000|PaperWidth=1000|Scale=100|PaperSource=15|PrintQuality=600|MediaType=1|DitherType=10|PaperKind=Letter|PrintScaleMode=1
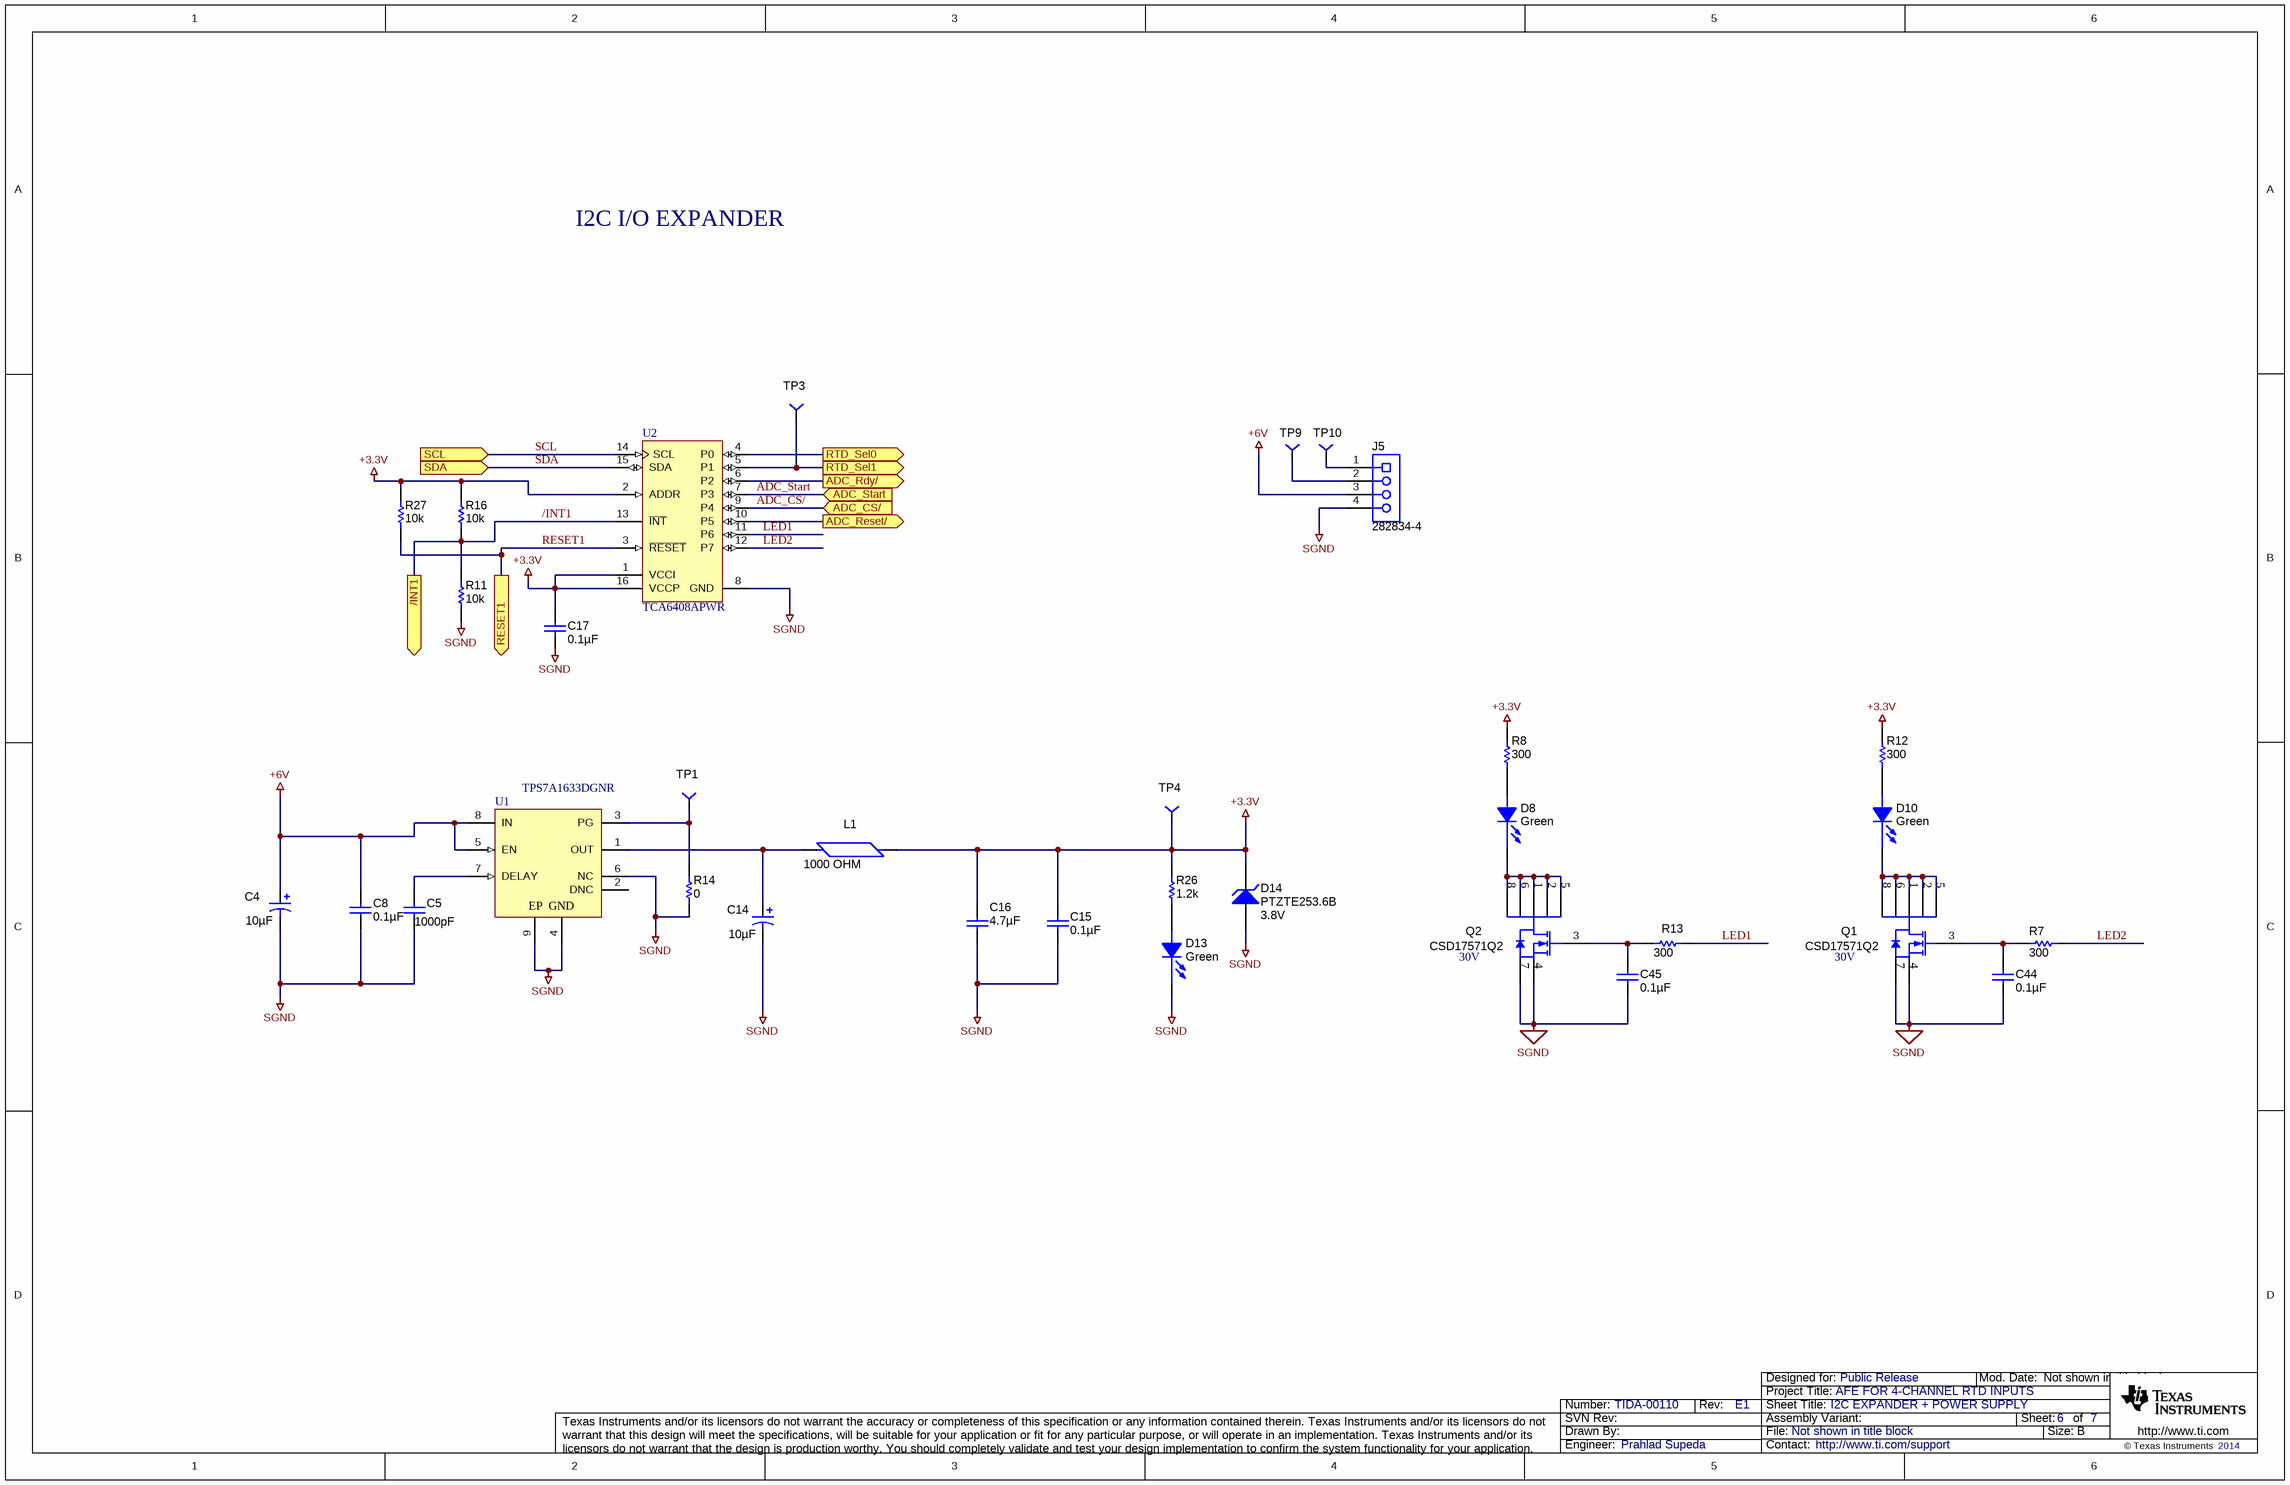
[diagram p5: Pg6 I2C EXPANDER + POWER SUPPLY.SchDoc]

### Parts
C4  ValueDisplayed: 10µF  [3528-21]  (hidden comment: F931C106KBA)
C5  ValueDisplayed: 1000pF  [0603]  (hidden comment: 06031C102JAT2A)
C8  ValueDisplayed: 0.1µF  [0603]  (hidden comment: 06035C104KAT2A)
C14  ValueDisplayed: 10µF  [3528-21]  (hidden comment: F931C106KBA)
C15  ValueDisplayed: 0.1µF  [0603]  (hidden comment: 06035C104KAT2A)
C16  ValueDisplayed: 4.7µF  [0805_HV]  (hidden comment: C2012X5R1H475K125AB)
C17  ValueDisplayed: 0.1µF  [0603]  (hidden comment: 06035C104KAT2A)
C44  ValueDisplayed: 0.1µF  [0603]  (hidden comment: 06033C104JAT2A)
C45  ValueDisplayed: 0.1µF  [0603]  (hidden comment: 06033C104JAT2A)
D8  value Green  [LED0603AA]  (hidden comment: LED_LG L29K-G2J1-24-Z)
D10  value Green  [LED0603AA]  (hidden comment: LED_LG L29K-G2J1-24-Z)
D13  value Green  [LED0603AA]  (hidden comment: LED_LG L29K-G2J1-24-Z)
D14  PTZTE253.6B  value 3.8V  [powerDI123]
J5  282834-4  [TEC_282834-4]
L1  1000 OHM  [FB0603]
Q1  CSD17571Q2  value 30V  [SON_CSD17571Q2]
Q2  CSD17571Q2  value 30V  [SON_CSD17571Q2]
R7  value 300  [0603]  (hidden comment: CRCW0603300RJNEA)
R8  value 300  [0603]  (hidden comment: CRCW0603300RJNEA)
R11  ValueDisplayed: 10k  [0603]  (hidden comment: CRCW060310K0JNEA)
R12  value 300  [0603]  (hidden comment: CRCW0603300RJNEA)
R13  value 300  [0603]  (hidden comment: CRCW0603300RJNEA)
R14  ValueDisplayed: 0  [0603]  (hidden comment: CRCW06030000Z0EA)
R16  ValueDisplayed: 10k  [0603]  (hidden comment: CRCW060310K0JNEA)
R26  ValueDisplayed: 1.2k  [0603]  (hidden comment: CRCW06031K20JNEAHP)
R27  ValueDisplayed: 10k  [0603]  (hidden comment: CRCW060310K0JNEA)
TP1  TP-038  [TP1_PD40_D0.5_S50]  (value not drawn)
TP3  TP-038  [TP1_PD40_D0.5_S50]  (value not drawn)
TP4  TP-038  [TP1_PD40_D0.5_S50]  (value not drawn)
TP9  TP-038  [TP1_PD40_D0.5_S50]  (value not drawn)
TP10  TP-038  [TP1_PD40_D0.5_S50]  (value not drawn)
U1  TPS7A1633DGNR  [DGN0008C_N]
U2  TCA6408APWR  [PW0016A_N]

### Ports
/INT1 (out), ADC_CS/ (in), ADC_Rdy/ (out), ADC_Reset/ (out), ADC_Start (in), RESET1 (out), RTD_Sel0 (out), RTD_Sel1 (out), SCL, SDA

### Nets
+3.3V: C15.2 C16.1 C17.1 D14.1(K) L1.2 R8.2 R12.2 R16.2 R26.2 R27.2 TP4.1 U2.1(VCCI) U2.2(ADDR) U2.16(VCCP)
+6V: C4.1(+) C8.2 J5.3 U1.5(EN) U1.8(IN)
SGND: C4.2(-) C5.2 C8.1 C14.2(-) C15.1 C16.2 C17.2 C44.2 C45.2 D13.1(C) D14.2(A) J5.4 Q1.4(S) Q1.7(S) Q2.4(S) Q2.7(S) R11.1 R14.1 U1.4(GND) U1.6(NC) U1.9(EP) U2.8(GND)
/INT1: R11.2 R16.1 U2.13(~{INT}) ; port /INT1
ADC_CS/: U2.9(P4) ; port ADC_CS/
ADC_Rdy/: U2.6(P2) ; port ADC_Rdy/
ADC_Reset/: U2.10(P5) ; port ADC_Reset/
ADC_Start: U2.7(P3) ; port ADC_Start
LED1: R13.1 U2.11(P6)
LED2: R7.1 U2.12(P7)
RESET1: R27.1 U2.3(~{RESET}) ; port RESET1
RTD_Sel0: U2.4(P0) ; port RTD_Sel0
RTD_Sel1: TP3.1 U2.5(P1) ; port RTD_Sel1
SCL: U2.14(SCL) ; port SCL
SDA: U2.15(SDA) ; port SDA
NetC5_1: C5.1 U1.7(DELAY)
NetC14_1: C14.1(+) L1.1 U1.1(OUT)
NetC44_1: C44.1 Q1.3(G) R7.2
NetC45_1: C45.1 Q2.3(G) R13.2
NetD8_1: D8.1(C) Q2.1(D) Q2.2(D) Q2.5(D) Q2.6(D) Q2.8(D)
NetD8_2: D8.2(A) R8.1
NetD10_1: D10.1(C) Q1.1(D) Q1.2(D) Q1.5(D) Q1.6(D) Q1.8(D)
NetD10_2: D10.2(A) R12.1
NetD13_2: D13.2(A) R26.1
NetJ5_1: J5.1 TP10.1
NetJ5_2: J5.2 TP9.1
NetR14_2: R14.2 TP1.1 U1.3(PG)

Not connected (* = marked no-connect by the designer): U1 2(DNC)

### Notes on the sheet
- I2C I/O EXPANDER

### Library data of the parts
C4 C14 = 293D106X9016B2TE3: as C20 on sheet Pg5 ADC + MULTIPLEXER
C5 = 06031C102JAT2A: CAP, CERM, 1000pF, 100V, +/-5%, X7R, 0603; Manufacturer: AVX; Polarized: N; CompType: Capacitor; U/M: EA; Cap_F: 0.000000001; Tolerance_%: 5; ESR_Ohm: 0.276; Value1: 0.276 ohm; VDC_V: 100; TaMin_C: -55; TaMax_C: 125
C8 C15 C17 = 06035C104KAT2A: as C19 on sheet Pg5 ADC + MULTIPLEXER
C16 = C2012X5R1H475K125AB: CAP, CERM, 4.7uF, 50V, +/-10%, X5R, 0805; Manufacturer: TDK; Polarized: N; CompType: Capacitor; U/M: EA; Cap_F: 0.0000047; Tolerance_%: 10; Value1: Unknown; VDC_V: 50; TaMin_C: -55; TaMax_C: 85; Cap_Case: 0805
C44 C45 = 06033C104JAT2A: CAP, CERM, 0.1uF, 25V, +/-5%, X7R, 0603; Manufacturer: AVX; Polarized: N; CompType: Capacitor; U/M: EA; Cap_F: 0.0000001; Tolerance_%: 5; ESR_Ohm: 0.05; Value1: 0.05 ohm; VDC_V: 25; TaMin_C: -55; TaMax_C: 125
D8 D10 D13 = LED_LG L29K-G2J1-24-Z: LED, SMARTLED, GREEN, 570NM,0603; Manufacturer: OSRAM OPTO SEMICONDUCTORS Inc; SymbolCreator: x0120606
D14 = PTZTE255.6B: DIODE ZENER 3.8V 1W PMDS; Manufacturer: Rohm Semiconductor; U/M: EA; Vz_V: 3.8
J5 = 282834-4: as J1 on sheet Pg3 CH1-CH3 RTD INTERFACE
L1 = MMZ1608B102C: FERRITE CHIP 1000 OHM 300MA 0603; Manufacturer: TDK Corporation; CompType: Ferrite Bead
Q1 Q2 = CSD17571Q2: MOSFET, N-CH, 30V, 22A, SON 2X2 MM; Manufacturer: TEXAS INSTRUMENTS; CompType: POWER MOSFET
R7 R8 R12 R13 = CRCW0603300RJNEA: RES, 300 ohm, 5%, 0.1W, 0603; Manufacturer: Vishay-Dale; CompType: Resistor; Value_Code: 300R; Tolerance_%: 5; Power_W: 0.1; VDC_V: 75; TempCo: 200 ppm/C; EIA_Code: E24; U/M: EA
R11 R16 R27 = CRCW060310K0JNEA: as R18 on sheet Pg5 ADC + MULTIPLEXER
R14 = CRCW06030000Z0EA: as R19 on sheet Pg5 ADC + MULTIPLEXER
R26 = CRCW06031K20JNEA: RES, 1.2 k, 5%, 0.1 W, 0603; Manufacturer: Vishay-Dale; CompType: Resistor; Res_ohm: 1200; Value: 1.2k; Value_Code: 1k20; Tolerance_%: 5; Power_W: 0.1; Value2: 0.1W; VDC_V: 75; TempCo: 200 ppm/C; EIA_Code: E24; U/M: EA
TP1 TP3 TP4 TP9 TP10 = TP-038: as TP2 on sheet Pg5 ADC + MULTIPLEXER
U1 = TPS7A1633DGNR: Single Output LDO, 100 mA, Fixed 3.3 V Output, 3 to 60 V Input, with Enable and Power Good, 8-pin MSOP (DGN), -40 to 125 degC, Green (RoHS & no Sb/Br); Manufacturer: Texas Instruments; Alternate Manufacturer: None; Alternate PartNumber: Equivalent; Accuracy(%): 2; Fixed Output Options(V): 3.3; Iout(Max)(A): 0.1; Iq(Typ)(mA): 0.004; Power Good: TRUE; Rating: Catalog; SubFamily: Single Channel LDO; Vdo(Typ)(mV): 60; Vin(Min)(V): 3
U2 = TCA6408APWR: Low-Voltage 8-Bit I2C and SMBus I/O Expander, 1.65 to 5.5 V, -40 to 85 degC, 16-pin TSSOP (PW), Green (RoHS & no Sb/Br); Manufacturer: Texas Instruments; Alternate Manufacturer: None; Alternate PartNumber: Equivalent; SubFamily: I2C IO Expander; No. of Outputs: 8; Interrupt Output: Yes; fSCLK(Max)(MHz): 400; VCC(Min)(V): 1.65; VCC(Max)(V): 5.5; I2C Address: 0100 00x

## Sheet Pg7 Hardware.SchDoc: Hardwares
size 431 x 279 mm; Date: Not shown in title block; ApprovedBy: Not shown in title block; CheckedBy: Not shown in title block; Author: Not shown in title block; CompanyName: Not shown in title block; Engineer: Not shown in title block; Organization: Not shown in title block; Address1: Not shown in title block; Address2: Not shown in title block; Address3: Not shown in title block; Address4: Not shown in title block; DocumentNumber: 8; Revision: Use project parameter SCH_Rev; SheetNumber: 7; SheetTotal: 7; PageSetup: Record=PageOptions|CenterHorizontal=True|CenterVertical=True|PrintScale=1.00|XCorrection=1.00|YCorrection=1.00|PrintKind=0|BorderSize=5000000|LeftOffset=0|BottomOffset=0|Orientation=2|PaperLength=1000|PaperWidth=1000|Scale=100|PaperSource=15|PrintQuality=600|MediaType=1|DitherType=10|PaperKind=Letter|PrintScaleMode=1
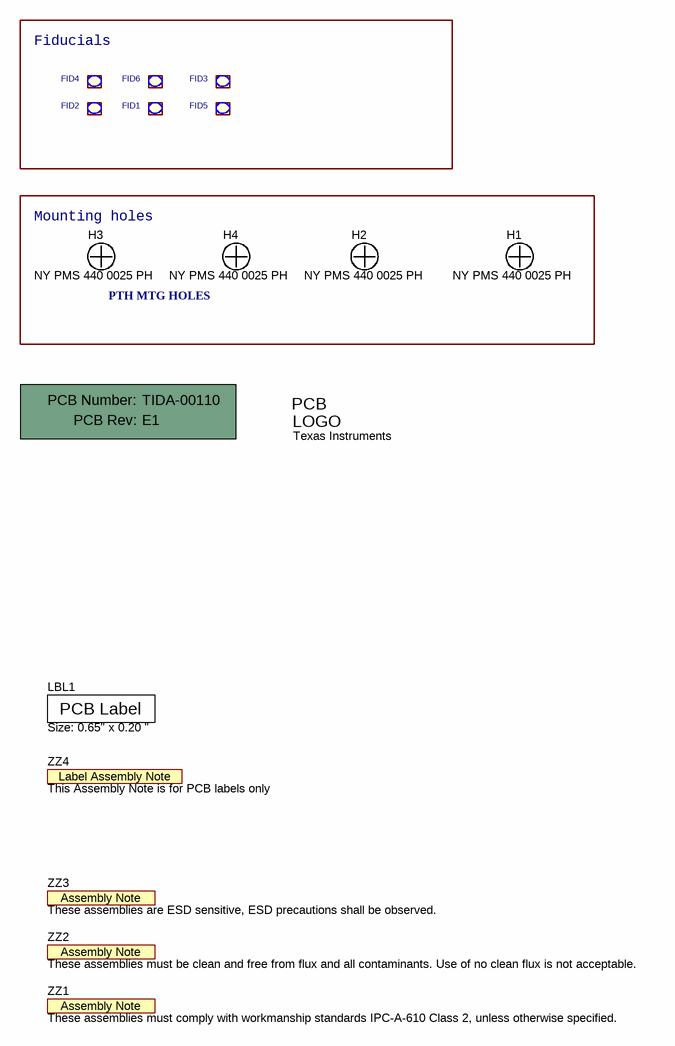
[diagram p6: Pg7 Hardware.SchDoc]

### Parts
!PCB1  Printed Circuit Board  (value not drawn)  (mechanical)
FID1  Fiducial40_80  [FID_TOP_40_80BA]  (value not drawn)
FID2  Fiducial40_80  [FID_TOP_40_80BA]  (value not drawn)
FID3  Fiducial40_80  [FID_TOP_40_80BA]  (value not drawn)
FID4  Fiducial40_80  [FID_TOP_40_80BA]  (value not drawn)
FID5  Fiducial40_80  [FID_TOP_40_80BA]  (value not drawn)
FID6  Fiducial40_80  [FID_TOP_40_80BA]  (value not drawn)
H1  NY PMS 440 0025 PH  [NY PMS 440 0025 PH]
H2  NY PMS 440 0025 PH  [NY PMS 440 0025 PH]
H3  NY PMS 440 0025 PH  [NY PMS 440 0025 PH]
H4  NY PMS 440 0025 PH  [NY PMS 440 0025 PH]
LBL1  Size: 0.65" x 0.20 "  [Label_650x200]
Logo1  Texas Instruments  [TI_Stacked_SolderMask_Small]  (no BOM)
ZZ1  These assemblies must comply with workmanship standards IPC-A-610 Class 2, unless otherwise specified.  [AssemblyNote]  (no BOM)
ZZ2  These assemblies must be clean and free from flux and all contaminants. Use of no clean flux is not acceptable.  [AssemblyNote]  (no BOM)
ZZ3  These assemblies are ESD sensitive, ESD precautions shall be observed.  [AssemblyNote]  (no BOM)
ZZ4  This Assembly Note is for PCB labels only  [AssemblyNoteLabel]  (no BOM)

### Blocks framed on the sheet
Fiducials: FID1-FID6
Mounting holes: H1-H4

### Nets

Not connected (* = marked no-connect by the designer): FID1 1; FID2 1; FID3 1; FID4 1; FID5 1; FID6 1

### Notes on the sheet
- (near H3) PTH MTG HOLES

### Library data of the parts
!PCB1 = PCB: Manufacturer: Any; PartNumber: TIDA-00110; SymbolCreator: a0412235
FID1-FID6 = Fiducial40_0
H1-H4 = NY PMS 440 0025 PH: Machine Screw, Round, #4-40 x 1/4, Nylon, Philips panhead; Manufacturer: B&F Fastener Supply; CompType: Hardware; SymbolCreator: codlsc; U/M: EA
LBL1 = THT-14-423-10: Thermal Transfer Printable Labels, 0.650" W x 0.200" H - 10,000 per roll; Manufacturer: Brady; SymbolCreator: a0412235; CompType: Label
Logo1 = TI_Logo: Texas Instrument Corporate Signature; SymbolCreator: codlsc
ZZ1-ZZ3 = AssemblyNote: SymbolCreator: codlsc
ZZ4 = AssemblyNoteLabel: SymbolCreator: a0412235

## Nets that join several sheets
+3.3V: Pg3 CH1-CH3 RTD INTERFACE (12 pins), Pg4 CH4 RTD INTERFACE (8 pins), Pg5 ADC + MULTIPLEXER (13 pins), Pg6 I2C EXPANDER + POWER SUPPLY (14 pins)
SGND: Pg3 CH1-CH3 RTD INTERFACE (18 pins), Pg4 CH4 RTD INTERFACE (15 pins), Pg5 ADC + MULTIPLEXER (19 pins), Pg6 I2C EXPANDER + POWER SUPPLY (22 pins)
SGND1: Pg3 CH1-CH3 RTD INTERFACE (18 pins), Pg4 CH4 RTD INTERFACE (12 pins)
/INT1: Pg5 ADC + MULTIPLEXER (R39.1), Pg6 I2C EXPANDER + POWER SUPPLY (R11.2 R16.1 U2.13)
ADC_CS/: Pg5 ADC + MULTIPLEXER (R46.2 U4.24), Pg6 I2C EXPANDER + POWER SUPPLY (U2.9)
ADC_Rdy/: Pg5 ADC + MULTIPLEXER (R42.2), Pg6 I2C EXPANDER + POWER SUPPLY (U2.6)
ADC_Reset/: Pg5 ADC + MULTIPLEXER (C25.1 R18.2 U4.4), Pg6 I2C EXPANDER + POWER SUPPLY (U2.10)
ADC_Start: Pg5 ADC + MULTIPLEXER (R50.2 U4.23), Pg6 I2C EXPANDER + POWER SUPPLY (U2.7)
RATIO: Pg3 CH1-CH3 RTD INTERFACE (J1.4 J2.4 J4.4), Pg4 CH4 RTD INTERFACE (5 pins)
RESET1: Pg5 ADC + MULTIPLEXER (R40.1), Pg6 I2C EXPANDER + POWER SUPPLY (R27.1 U2.3)
RTD1_IEXC1: Pg3 CH1-CH3 RTD INTERFACE (D31.2), Pg5 ADC + MULTIPLEXER (R19.1)
RTD1_IEXC2: Pg3 CH1-CH3 RTD INTERFACE (D5.2), Pg5 ADC + MULTIPLEXER (R33.2)
RTD2_IEXC1: Pg3 CH1-CH3 RTD INTERFACE (D32.2), Pg5 ADC + MULTIPLEXER (R20.1)
RTD2_IEXC2: Pg3 CH1-CH3 RTD INTERFACE (D18.2), Pg5 ADC + MULTIPLEXER (R34.2)
RTD3_IEXC1: Pg3 CH1-CH3 RTD INTERFACE (D33.2), Pg5 ADC + MULTIPLEXER (R21.1)
RTD3_IEXC2: Pg3 CH1-CH3 RTD INTERFACE (D34.2), Pg5 ADC + MULTIPLEXER (R35.2)
RTD4_IEXC1: Pg4 CH4 RTD INTERFACE (D36.2), Pg5 ADC + MULTIPLEXER (R22.1)
RTD4_IEXC2: Pg4 CH4 RTD INTERFACE (D35.2), Pg5 ADC + MULTIPLEXER (R36.2)
RTD_AINN1: Pg3 CH1-CH3 RTD INTERFACE (R6.1), Pg5 ADC + MULTIPLEXER (U4.12)
RTD_AINN2: Pg3 CH1-CH3 RTD INTERFACE (R31.1), Pg5 ADC + MULTIPLEXER (U4.14)
RTD_AINN3: Pg3 CH1-CH3 RTD INTERFACE (R49.1), Pg5 ADC + MULTIPLEXER (U4.16)
RTD_AINN4: Pg4 CH4 RTD INTERFACE (R53.1), Pg5 ADC + MULTIPLEXER (U4.18)
RTD_AINP1: Pg3 CH1-CH3 RTD INTERFACE (R5.1), Pg5 ADC + MULTIPLEXER (U4.11)
RTD_AINP2: Pg3 CH1-CH3 RTD INTERFACE (R32.1), Pg5 ADC + MULTIPLEXER (U4.13)
RTD_AINP3: Pg3 CH1-CH3 RTD INTERFACE (R48.1), Pg5 ADC + MULTIPLEXER (U4.15)
RTD_AINP4: Pg4 CH4 RTD INTERFACE (R52.1), Pg5 ADC + MULTIPLEXER (U4.17)
RTD_REFN0: Pg4 CH4 RTD INTERFACE (R17.1), Pg5 ADC + MULTIPLEXER (U4.8)
RTD_REFP0: Pg4 CH4 RTD INTERFACE (R15.1), Pg5 ADC + MULTIPLEXER (U4.7)
RTD_Sel0: Pg5 ADC + MULTIPLEXER (R37.2), Pg6 I2C EXPANDER + POWER SUPPLY (U2.4)
RTD_Sel1: Pg5 ADC + MULTIPLEXER (R23.1), Pg6 I2C EXPANDER + POWER SUPPLY (TP3.1 U2.5)
SCL: Pg5 ADC + MULTIPLEXER (J3.8 R56.1), Pg6 I2C EXPANDER + POWER SUPPLY (U2.14)
SDA: Pg5 ADC + MULTIPLEXER (J3.7 R57.1), Pg6 I2C EXPANDER + POWER SUPPLY (U2.15)

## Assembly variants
001: not fitted C6 C7 C11 C13 C18 C24 C25 C27 C33 C35 C36 D6 D7 D9 D11 D16 D17 D22 D24 D25 D26 FID1 FID2 FID3 FID4 FID5 FID6 H1 H2 H3 H4 LBL1 R11 R14 R46 R50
